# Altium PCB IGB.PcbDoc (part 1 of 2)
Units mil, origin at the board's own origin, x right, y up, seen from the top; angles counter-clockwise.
Board outline 7000 x 12000 mil, 4 copper layers (Top Layer, GND, PWR, Bottom Layer), stack 55.52 mil thick; 229 components, 204 nets, 726 pads, 127 vias.
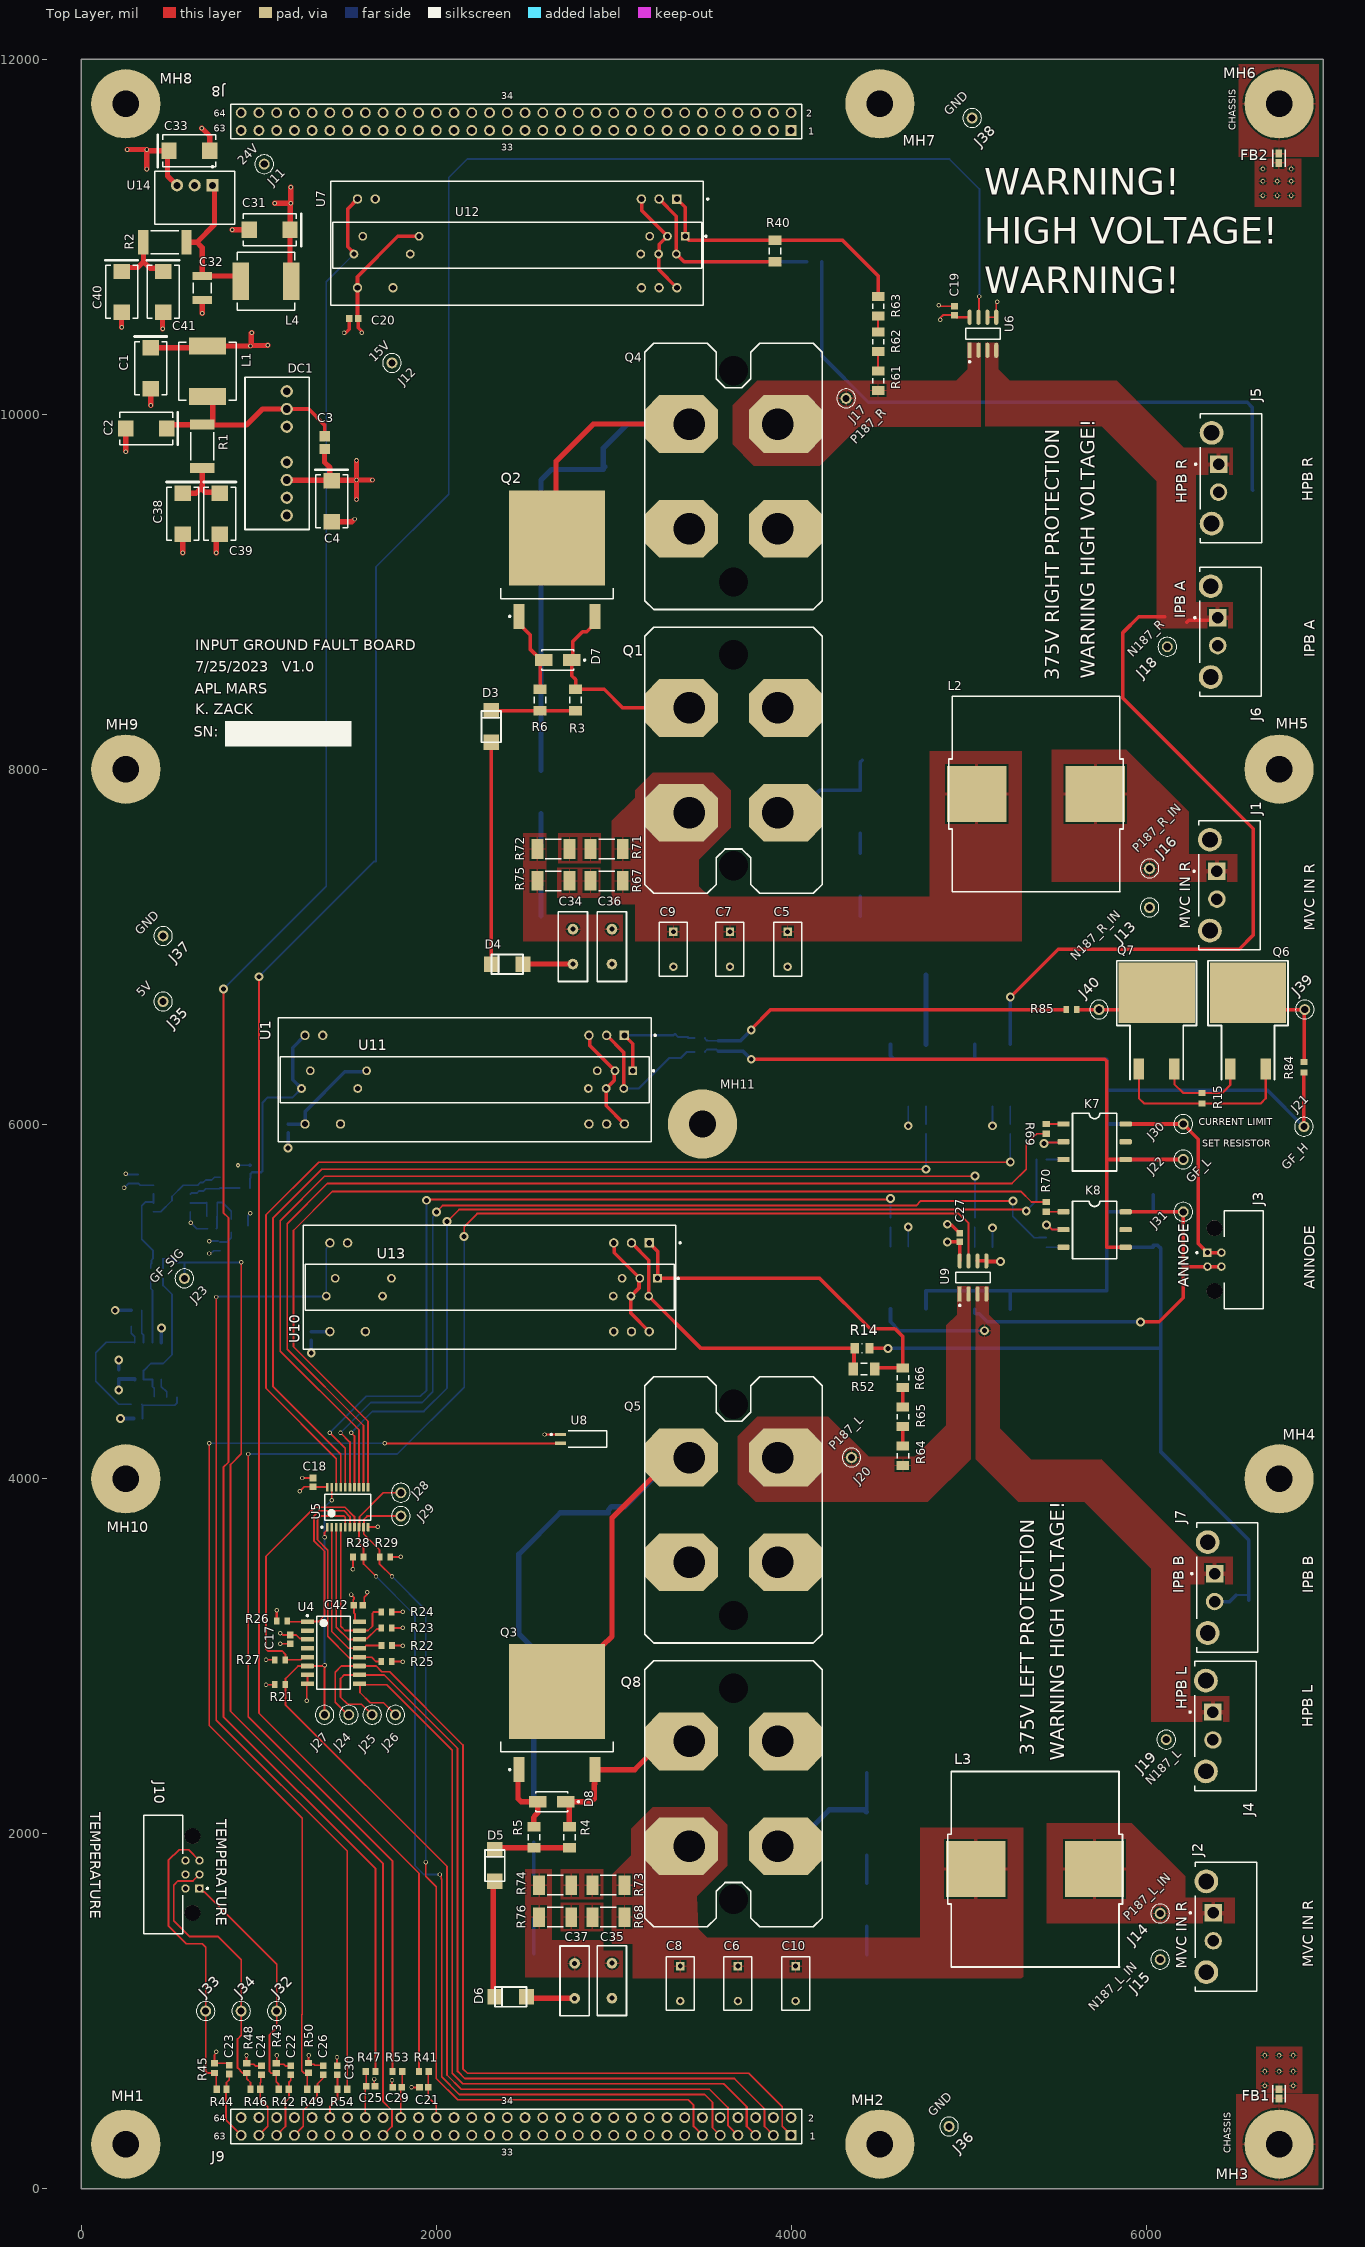
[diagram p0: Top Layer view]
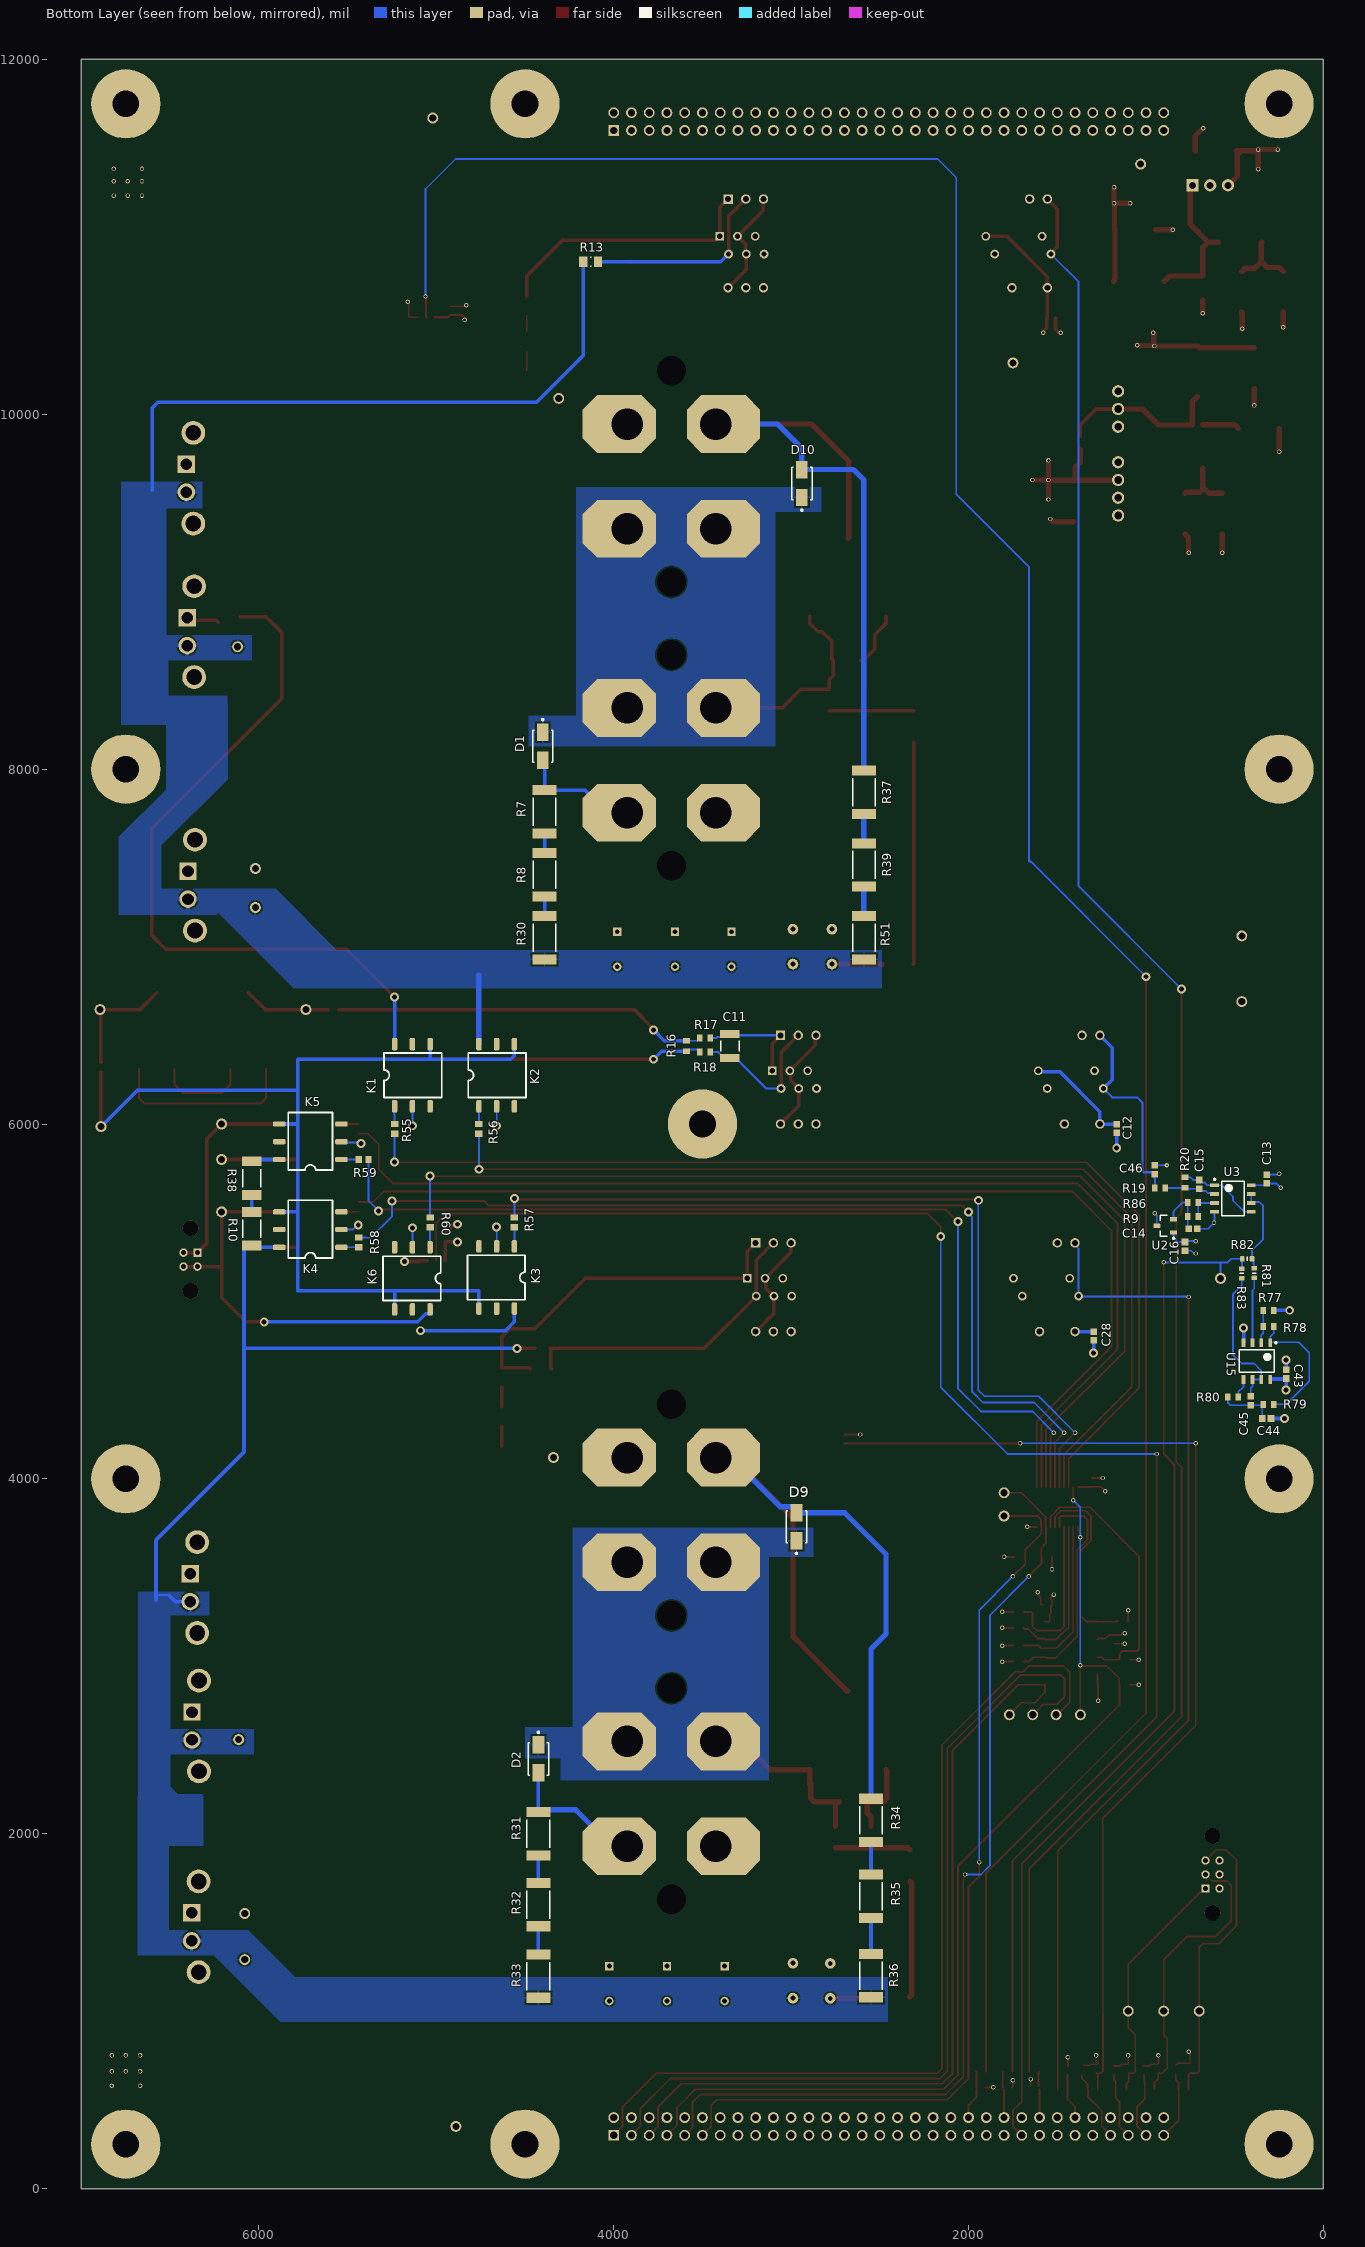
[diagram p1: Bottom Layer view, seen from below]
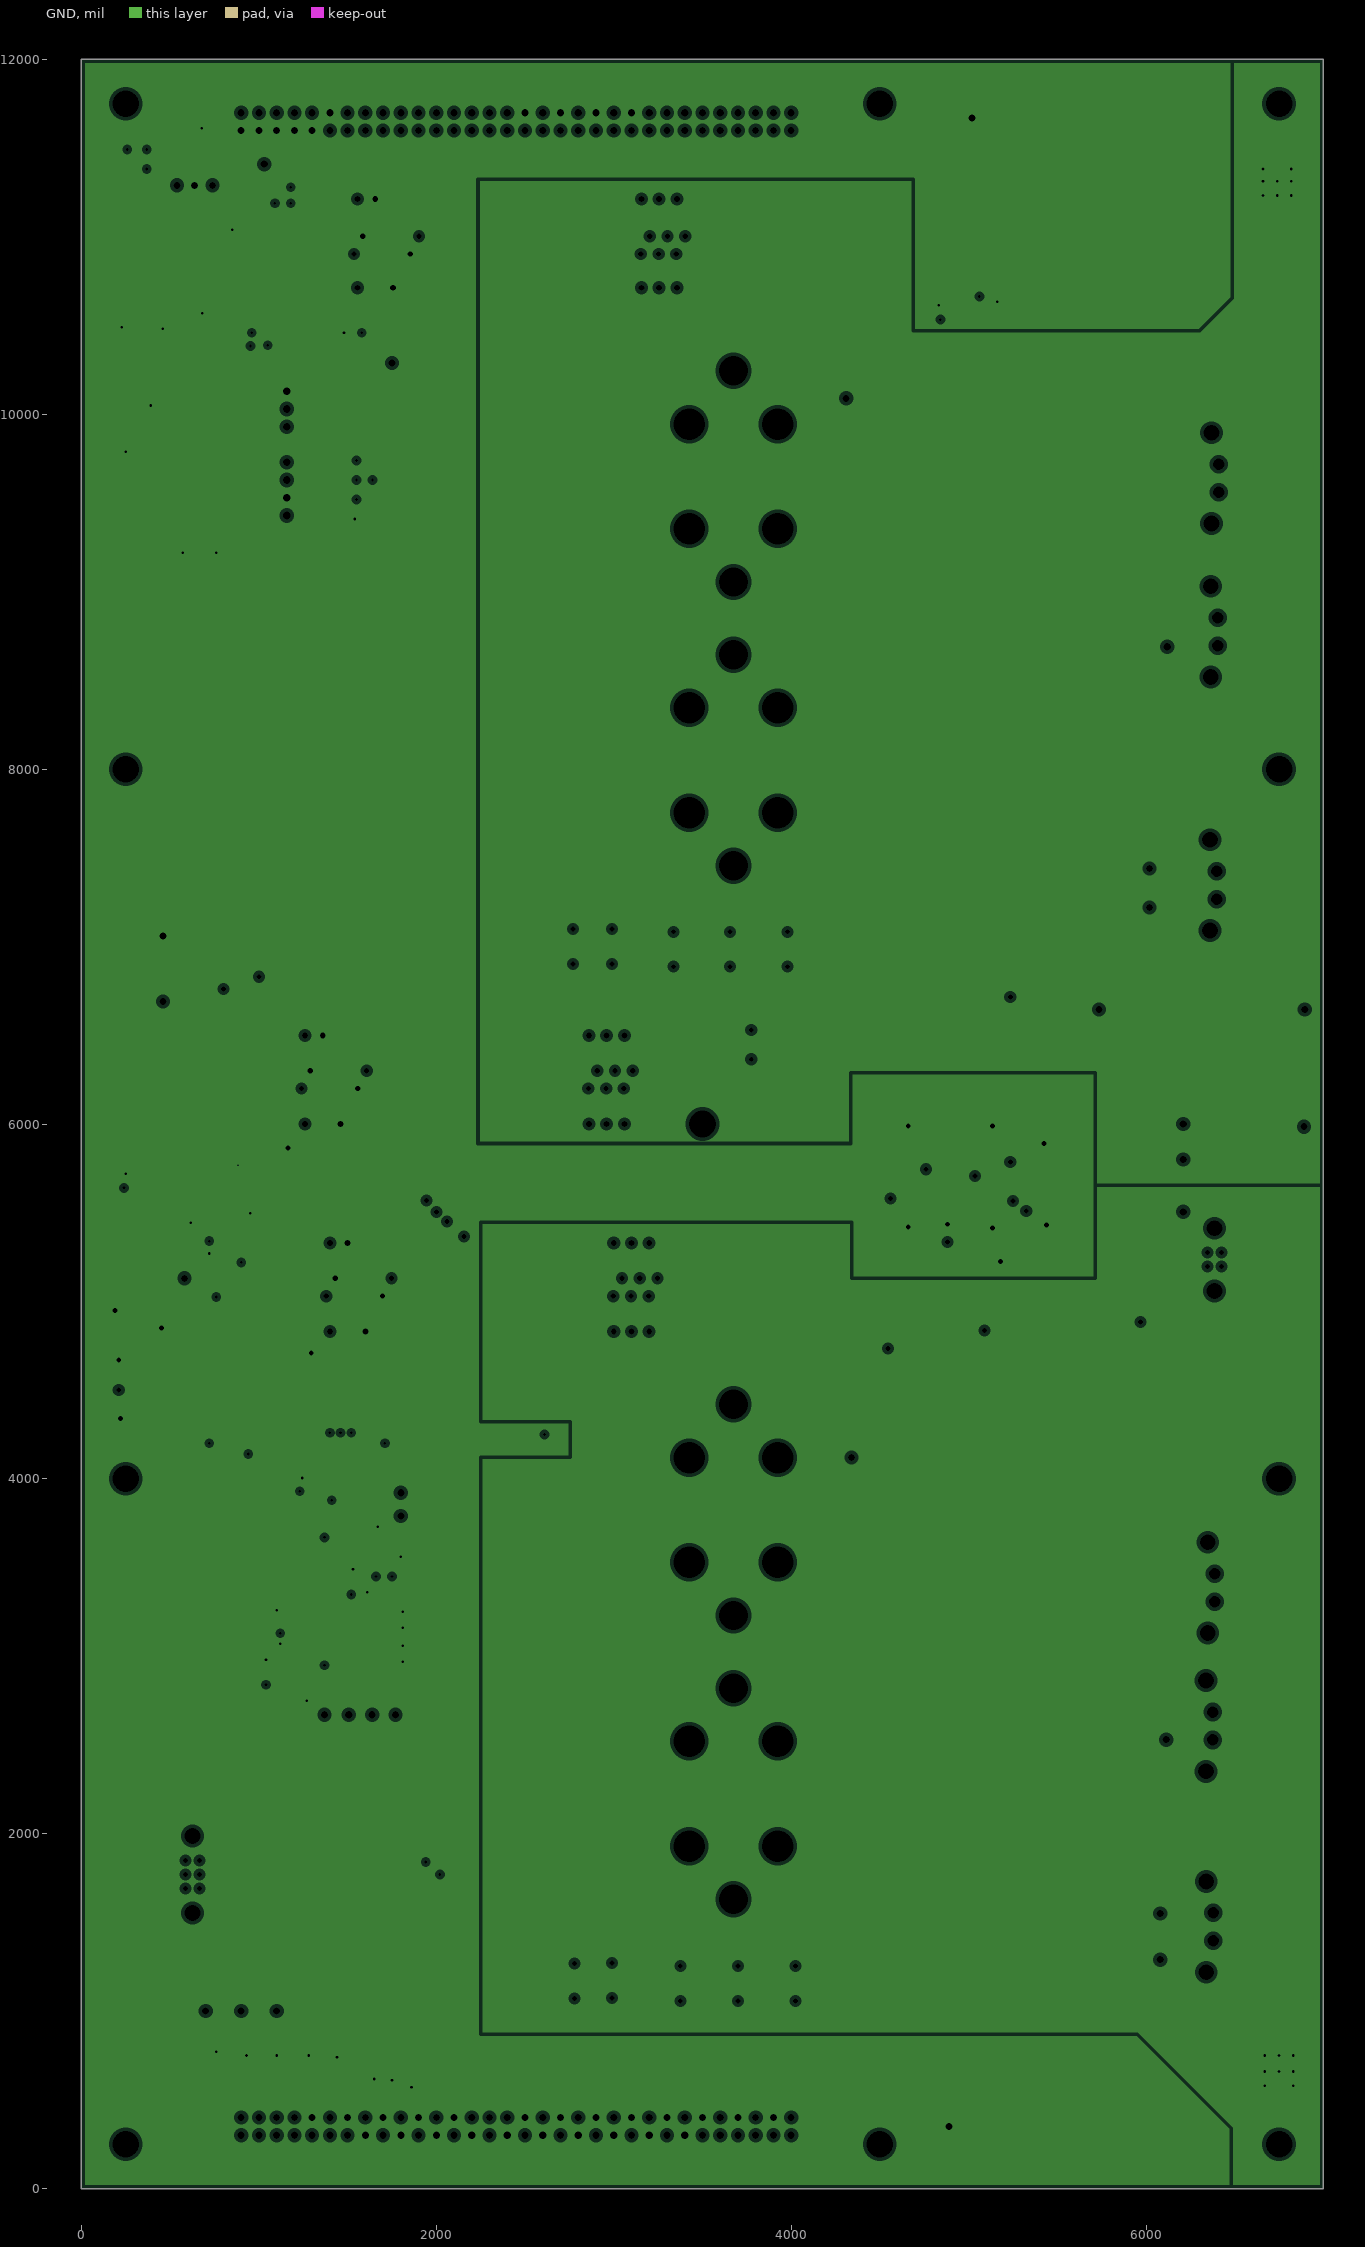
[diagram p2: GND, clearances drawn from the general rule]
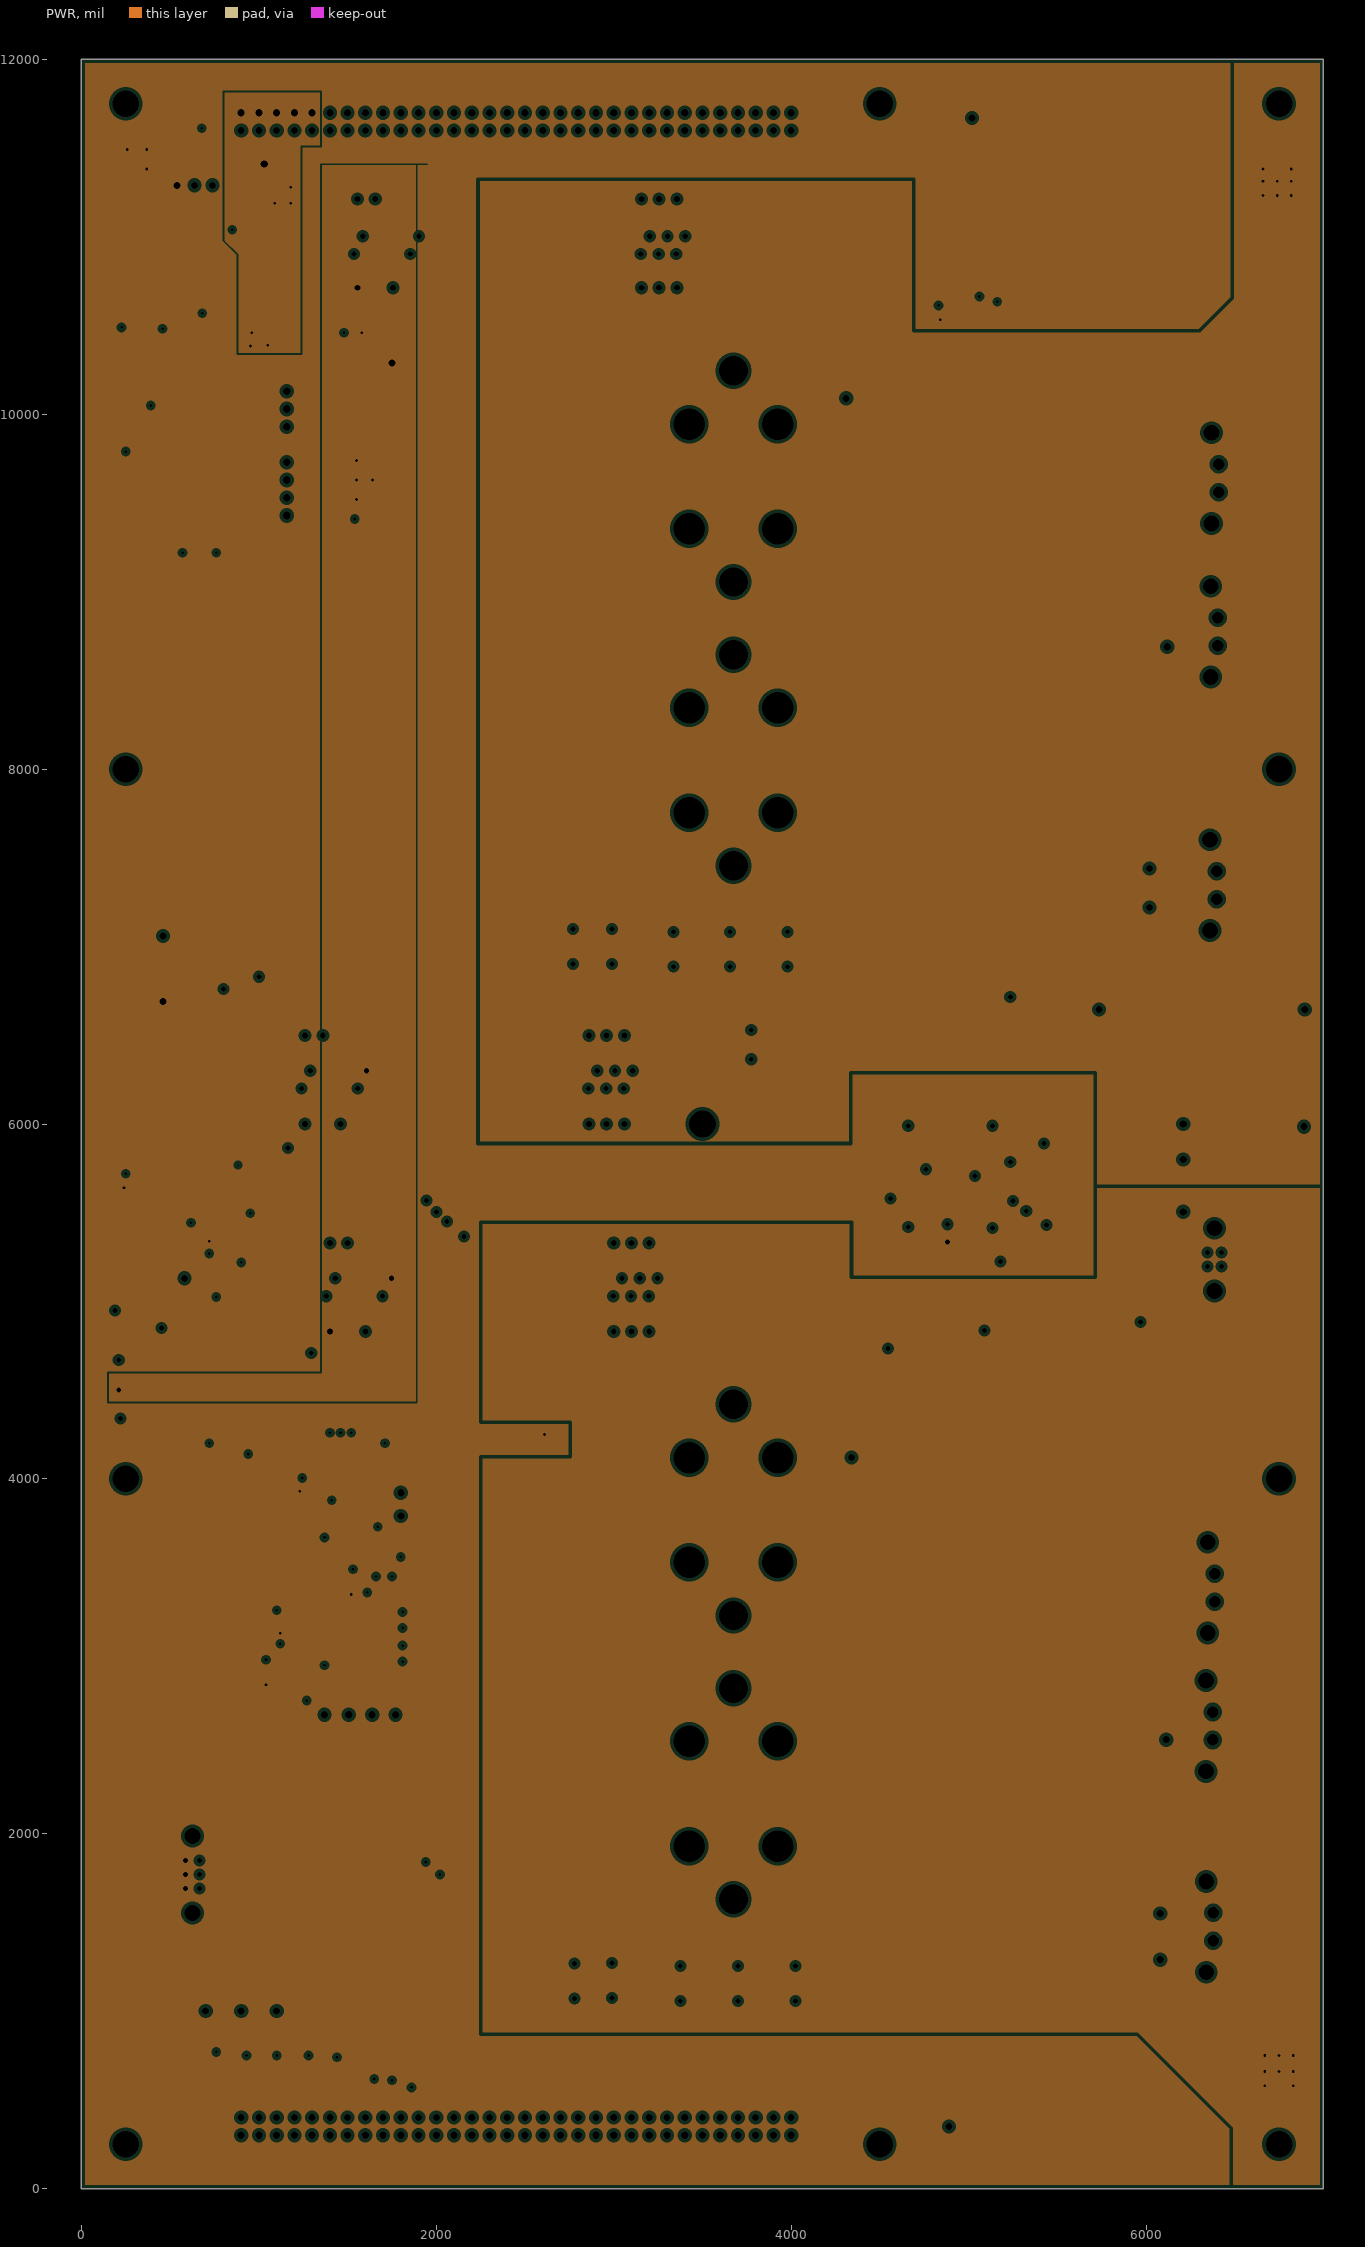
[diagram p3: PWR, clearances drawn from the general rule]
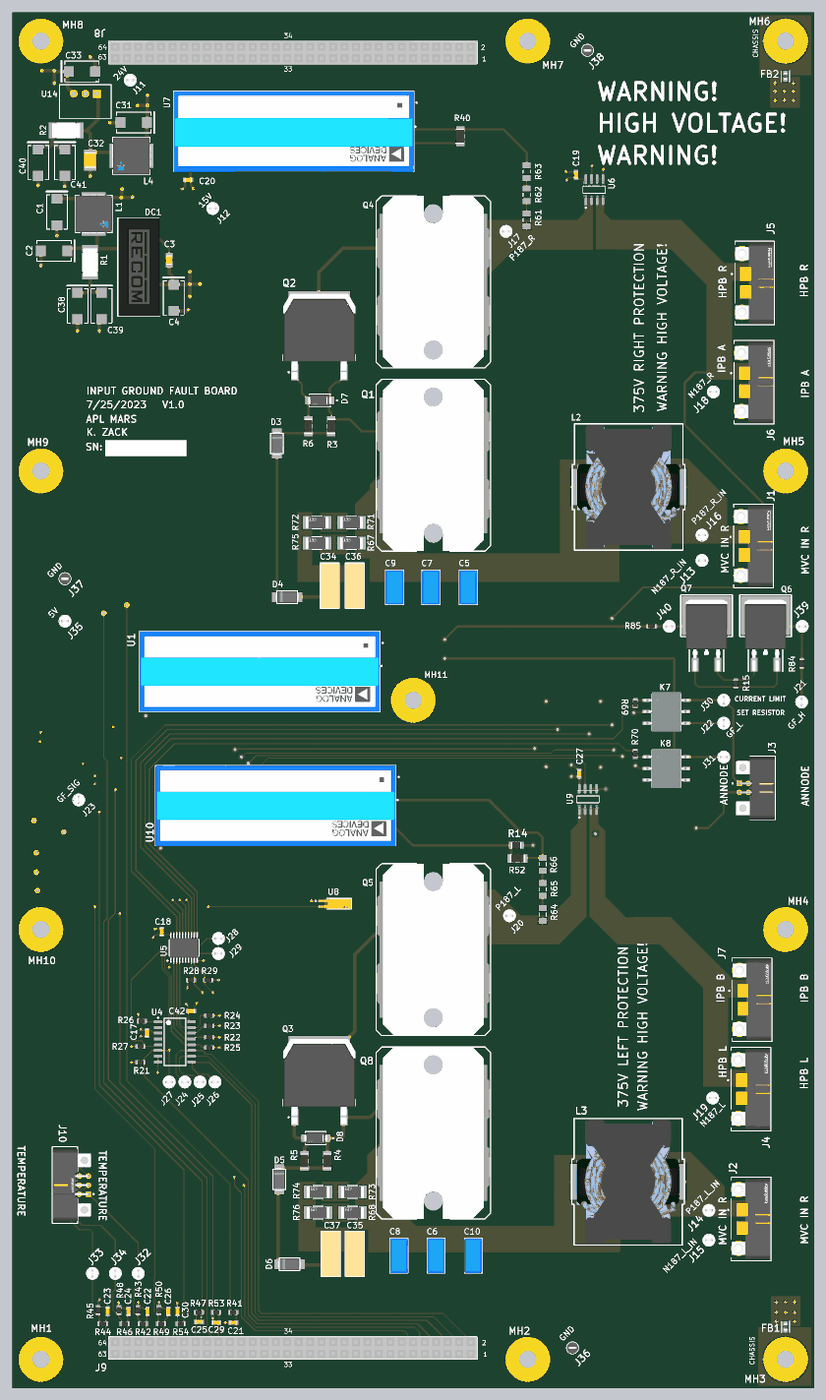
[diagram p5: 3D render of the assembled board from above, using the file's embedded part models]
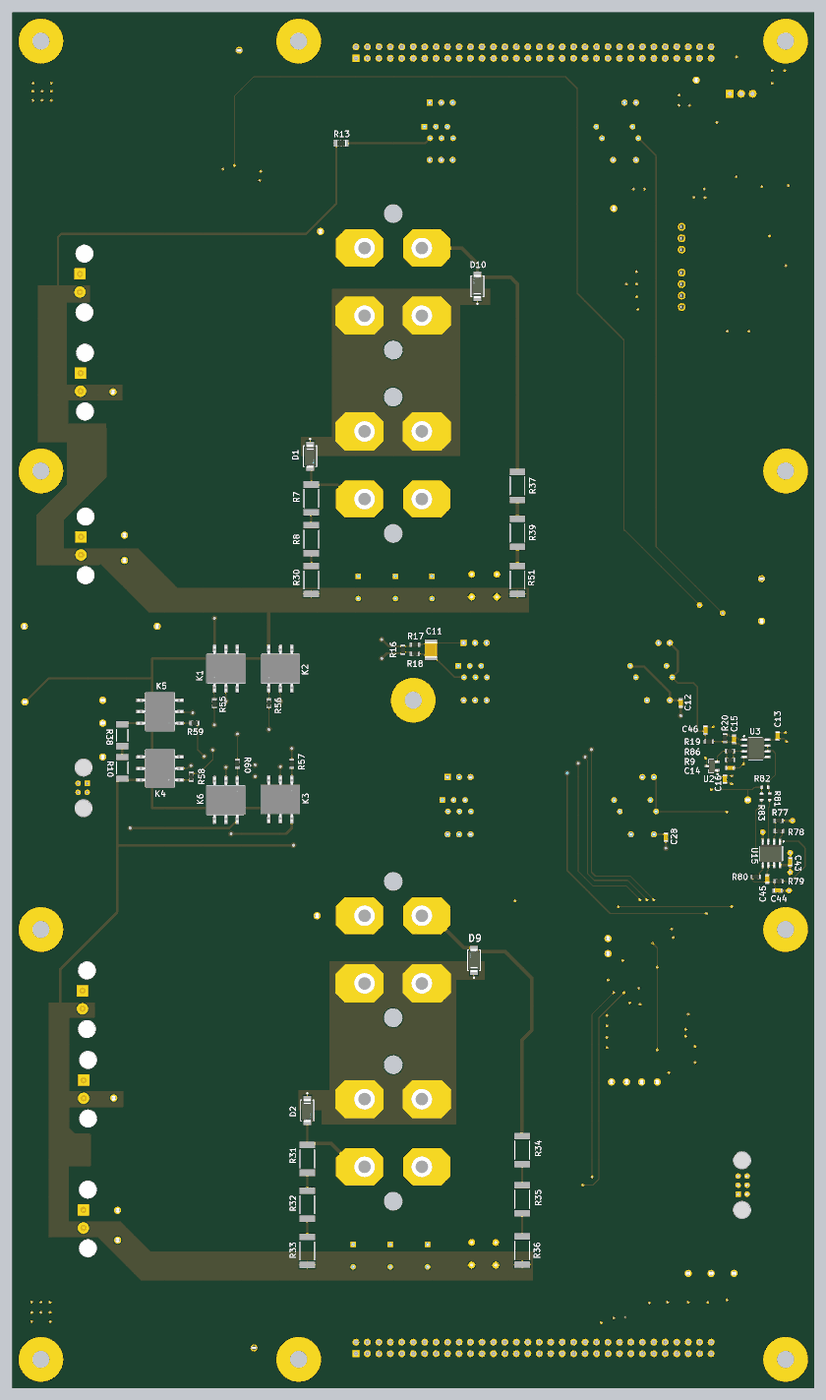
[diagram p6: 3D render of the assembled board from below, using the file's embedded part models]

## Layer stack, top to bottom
Top Solder: solder mask 0.4, Solder Resist, Dk 3.5
Top Layer: signal copper 1.7
Dielectric 1: prepreg 7.96, PP-013, Dk 4.3
GND: plane copper 0.68, net (Multiple Nets)
Core 1: core 39, FR-4, Dk 4.8
PWR: plane copper 0.68, net (Multiple Nets)
Dielectric 2: prepreg 3.8, PP-013, Dk 4.3
Bottom Layer: signal copper 1.7
Bottom Solder: solder mask 0.4, Solder Resist, Dk 3.5

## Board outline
0,0 0,12000 7000,12000 7000,0

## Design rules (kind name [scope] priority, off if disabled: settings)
Clearance [All] p1: gap=8 ignorepadtopadclearanceinfootprint=FALSE except(0: Arc-Hole Track-Hole SMDPad-Hole THPad-Hole Via-Hole Fill-Hole Poly-Hole Region-Hole Text-Hole; 10: SMDPad-THPad SMDPad-Via SMDPad-Text THPad-THPad THPad-Via THPad-Text Via-Via Via-Text Fill-Text Poly-Text Region-Text Text-Text)
ComponentClearance "Amplifier Exception Voltage R" [InComponent('U7') vs InComponent('U12')] p1: gap=0 collisioncheckmode=3 verticalgap=0 showdistances=FALSE checkcomponentboundary=TRUE
ComponentClearance "Amplifier Exception Voltage L" [InComponent('U10') vs InComponent('U13')] p2: gap=0 collisioncheckmode=3 verticalgap=0 showdistances=FALSE checkcomponentboundary=TRUE
ComponentClearance "Amplifier Exception GF" [InComponent('U11') vs InComponent('U1')] p3: gap=0 collisioncheckmode=3 verticalgap=0 showdistances=FALSE donotcheckwithout3dbody=TRUE // U1 Clearance
ComponentClearance [All] p4: gap=10 collisioncheckmode=3 verticalgap=10 showdistances=FALSE
HoleSize [All] p1: absolutevalues=TRUE maxlimit=250 minlimit=1 maxpercent=80.000 minpercent=20.000
MinimumSolderMaskSliver [All] p1: minsoldermaskwidth=3.8
PlaneClearance [All] p1: clearance=20
PlaneConnect [All] p1: planeconnectstyle=Relief reliefexpansion=20 reliefentries=4 reliefconductorwidth=10 reliefairgap=10
PolygonConnect [All] p1: connectstyle=Relief reliefconductorwidth=10 reliefentries=4 polygonreliefangle="90 Angle" airgapwidth=10
RoutingVias [All] p1: holewidth=28 width=50 viastyle="Through Hole" minholewidth=28 minwidth=50 maxholewidth=28 maxwidth=50
SolderMaskExpansion [All] p1: expansion=4 istentingtop=FALSE
Width [All] p1: maxlimit=100 minlimit=6 preferedwidth=20 minimp=50.000000 maximp=50.000000 favimp=50.000000
25 further rules are at their usual default settings.

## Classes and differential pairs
component class Sensors: C19 C20 C21 C22 C23 C24 C25 C26 C27 C28 C29 C30 J32 J33 J34 R40 R41 R42 R43 R44 R45 R46 R47 R48 R49 R50 R52 R53 R54 R61 R62 R63 R64 R65 R66 U6 U7 U8 U9 U10 U12 U13
component class "Power Suppies": C1 C2 C3 C4 C31 C32 C33 C38 C39 C40 C41 DC1 J11 J12 J35 J36 J37 J38 L1 L4 R1 R2 U14
component class "GF Switch": C17 C18 C42 J24 J25 J26 J27 J28 J29 J30 J31 K1 K2 K3 K4 K5 K6 K7 K8 R10 R21 R22 R23 R24 R25 R26 R27 R28 R29 R38 R55 R56 R57 R58 R59 R60 R69 R70 U4 U5
component class "GF Detect": C11 C12 C13 C14 C15 C16 C43 C44 C45 C46 J21 J22 J23 J39 J40 Q6 Q7 R9 R15 R16 R17 R18 R19 R20 R77 R78 R79 R80 R81 R82 R83 R84 R85 R86 U1 U2 U3 U11 U15
component class U_Connectors: J1 J2 J3 J4 J5 J6 J7 J8 J9 J10
component class Input: C5 C6 C7 C8 C9 C10 C34 C35 C36 C37 D1 D2 D3 D4 D5 D6 D7 D8 D9 D10 J13 J14 J15 J16 J17 J18 J19 J20 L2 L3 Q1 Q2 Q3 Q4 Q5 Q8 R3 R4 R5 R6 R7 R8 R13 R14 R30 R31 R32 R33 R34 R35 R36 R37 R39 R51 R67 R68 R71 R72 R73 R74 R75 R76
component class Coversheet: FB1 FB2 MH1 MH2 MH3 MH4 MH5 MH6 MH7 MH8 MH9 MH10 MH11

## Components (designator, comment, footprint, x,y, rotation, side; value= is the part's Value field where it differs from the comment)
C1 "T491D106K050AT" KEMT-D-7343-31-2_L 390,10260 r270 top value=10uF
C2 "T491D106K050AT" KEMT-D-7343-31-2_L 364.84,9920 r180 top value=10uF
C3 "Capacitor 330pF 10%, 50V, X7R, 0805" CAPC2013X95X50ML10T25 1370,9840 r270 top value=330pF
C4 "T491D106K050AT" KEMT-D-7343-31-2_L 1410,9510 r270 top value=10uF
C5 "Capacitor 0.22uF, 20%, 1kV,X7R,Radial" FP-RDEUE1+0_5-MFG 3980,6985 r270 top value=220nF
C6 "Capacitor 0.22uF, 20%, 1kV,X7R,Radial" FP-RDEUE1+0_5-MFG 3700,1155 r270 top value=220nF
C7 "Capacitor 0.22uF, 20%, 1kV,X7R,Radial" FP-RDEUE1+0_5-MFG 3655,6985 r270 top value=220nF
C8 "Capacitor 0.22uF, 20%, 1kV,X7R,Radial" FP-RDEUE1+0_5-MFG 3375,1155 r270 top value=220nF
C9 "Capacitor 0.22uF, 20%, 1kV,X7R,Radial" FP-RDEUE1+0_5-MFG 3336.26,6985 r270 top value=220nF
C10 "Capacitor 0.22uF, 20%, 1kV,X7R,Radial" FP-RDEUE1+0_5-MFG 4025,1155 r270 top value=220nF
C11 "Capacitor 2.2uF 10%, 50V, X7R, 1210" CAPC3225X270X30ML30 3345,6440 r90 bottom value=2.2uF
C12 "Capacitor 100 nF +/-10% 50 V 0603" CAPC1608X90X40NL10T20 1165,5975 r90 bottom value=100nF
C13 "Capacitor 100 nF +/-10% 50 V 0603" CAPC1608X90X40NL10T20 320,5690 r270 bottom value=100nF
C14 "Capacitor 100 nF +/-10% 50 V 0603" CAPC1608X90X40NL10T20 735,5410 r0 bottom value=100nF
C15 "Capacitor 100 nF +/-10% 50 V 0603" CAPC1608X90X40NL10T20 700,5660 r90 bottom value=100nF
C16 "Capacitor 100 nF +/-10% 50 V 0603" CAPC1608X90X40NL10T20 780,5310 r90 bottom value=100nF
C17 "Capacitor 100 nF +/-10% 50 V 0603" CAPC1608X90X40NL10T20 1175.74,3095.5 r90 top value=100nF
C18 "Capacitor 100 nF +/-10% 50 V 0603" CAPC1608X90X40NL10T20 1304.95,3980 r270 top value=100nF
C19 "Capacitor 100 nF +/-10% 50 V 0603" CAPC1608X90X40NL10T20 4921,10584 r270 top value=100nF
C20 "Capacitor 100 nF +/-10% 50 V 0603" CAPC1608X90X40NL10T20 1534.61,10540 r0 top value=100nF
C21 "Capacitor 100 nF +/-10% 50 V 0603" CAPC1608X90X40NL10T20 1930,570 r0 top value=100nF
C22 "Capacitor 100 nF +/-10% 50 V 0603" CAPC1608X90X40NL10T20 1180,666.47 r270 top value=100nF
C23 "Capacitor 100 nF +/-10% 50 V 0603" CAPC1608X90X40NL10T20 832.84,670 r270 top value=100nF
C24 "Capacitor 100 nF +/-10% 50 V 0603" CAPC1608X90X40NL10T20 1014.31,666.47 r270 top value=100nF
C25 "Capacitor 100 nF +/-10% 50 V 0603" CAPC1608X90X40NL10T20 1630,577.16 r180 top value=100nF
C26 "Capacitor 100 nF +/-10% 50 V 0603" CAPC1608X90X40NL10T20 1362.84,666.47 r270 top value=100nF
C27 "Capacitor 100 nF +/-10% 50 V 0603" CAPC1608X90X40NL10T20 4950,5360 r270 top value=100nF
C28 "Capacitor 100 nF +/-10% 50 V 0603" CAPC1608X90X40NL10T20 1295,4805.39 r90 bottom value=100nF
C29 "Capacitor 100 nF +/-10% 50 V 0603" CAPC1608X90X40NL10T20 1780,570 r0 top value=100nF
C30 "Capacitor 100 nF +/-10% 50 V 0603" CAPC1608X90X40NL10T20 1442.44,666.47 r270 top value=100nF
C31 "T491D106K050AT" KEMT-D-7343-31-2_L 1060,11040 r180 top value=10uF
C32 "Capacitor 4.7uF 10%, 50V, X7R, 1210" CAPC3225X270X30ML30 680,10712.09 r90 top value=4.7uF
C33 "T491D106K050AT" KEMT-D-7343-31-2_L 608.16,11485 r0 top value=10uF
C34 "Capacitor 1.2uF 20% 500V X7R" "Capacitor 1.2uF 20% 500V X7R-Footprint-1" 2770,7000 r90 top value=1.2uF
C35 "Capacitor 1.2uF 20% 500V X7R" "Capacitor 1.2uF 20% 500V X7R-Footprint-1" 2990,1171.57 r90 top value=1.2uF
C36 "Capacitor 1.2uF 20% 500V X7R" "Capacitor 1.2uF 20% 500V X7R-Footprint-1" 2990,7000 r90 top value=1.2uF
C37 "Capacitor 1.2uF 20% 500V X7R" "Capacitor 1.2uF 20% 500V X7R-Footprint-1" 2779.61,1170.39 r90 top value=1.2uF
C38 "T491D106K050AT" KEMT-D-7343-31-2_L 570,9440 r270 top value=10uF
C39 "T491D106K050AT" KEMT-D-7343-31-2_L 780,9440 r270 top value=10uF
C40 "T491D106K050AT" KEMT-D-7343-31-2_L 226.02,10690 r270 top value=10uF
C41 "T491D106K050AT" KEMT-D-7343-31-2_L 460,10690 r270 top value=10uF
C42 "Capacitor 100 nF +/-10% 50 V 0603" CAPC1608X90X40NL10T20 1560,3287.88 r180 top value=100nF
C43 "Capacitor 100 nF +/-10% 50 V 0603" CAPC1608X90X40NL10T20 210,4590 r270 bottom value=100nF
C44 "Capacitor 100 nF +/-10% 50 V 0603" CAPC1608X90X40NL10T20 320,4340 r0 bottom value=100nF
C45 "Capacitor 100 nF +/-10% 50 V 0603" CAPC1608X90X40NL10T20 410,4440 r90 bottom value=100nF
C46 "Capacitor 100 nF +/-10% 50 V 0603" CAPC1608X90X40NL10T20 950,5742 r270 bottom value=100nF
D1 "SMAZ15-13-F" FP-SMA-MFG 4400,8128.74 r270 bottom
D2 "SMAZ15-13-F" FP-SMA-MFG 4425,2421.26 r270 bottom
D3 "BZG03C200-M3-08" BZG03C200-M3-08-Footprint-1 2310,8240 r90 top
D4 "BZG03C200-M3-08" BZG03C200-M3-08-Footprint-1 2400,6900 r180 top
D5 "BZG03C200-M3-08" BZG03C200-M3-08-Footprint-1 2330,1820 r90 top
D6 "BZG03C200-M3-08" BZG03C200-M3-08-Footprint-1 2420,1080 r180 top
D7 "SMAZ15-13-F" FP-SMA-MFG 2685,8615 r180 top
D8 "SMAZ15-13-F" FP-SMA-MFG 2650,2180 r180 top
D9 "SMAZ15-13-F" FP-SMA-MFG 2970,3730 r90 bottom
D10 "SMAZ15-13-F" FP-SMA-MFG 2940,9610 r90 bottom
DC1 "RS3-2415S/H3" RS3-2415S_H3-Footprint-1 1057.18,9780 r270 top
FB1 "BLM18SG121TN1D" FP-BLM18-0_15-t0_5-d1_2-IPC_B 6750,533.38 r270 top
FB2 "BLM18SG121TN1D" FP-BLM18-0_15-t0_5-d1_2-IPC_B 6749,11443 r90 top
J1 "M80-5000000M5-02-333-00-000" FP-M80-5000000M5-02-333-0-MFG 6470.48,7346.26 r90 top
J2 "M80-5000000M5-02-333-00-000" FP-M80-5000000M5-02-333-0-MFG 6450,1475 r90 top
J3 "M80-5400442" M80-5400442-Footprint-1 6385.63,5235.63 r90 top
J4 "M80-5000000M5-02-333-00-000" FP-M80-5000000M5-02-333-0-MFG 6448,2607 r90 top
J5 "M80-5000000M5-02-333-00-000" FP-M80-5000000M5-02-333-0-MFG 6480,9640 r90 top
J6 "M80-5000000M5-02-333-00-000" FP-M80-5000000M5-02-333-0-MFG 6475,8775 r90 top
J7 "M80-5000000M5-02-333-00-000" FP-M80-5000000M5-02-333-0-MFG 6458,3387 r90 top
J8 "ESQ-132-14-G-D" SMTC-ESQ-132-14-X-D 4000,11600 r180 top
J9 "ESQ-132-14-G-D" SMTC-ESQ-132-14-X-D 4000,300 r180 top
J10 "M80-5400642" FP-M80-5400642-MFG 460,1770 r270 top
J11 "5002" FP-5002-MFG 1030,11410 r180 top
J12 "5002" FP-5002-MFG 1750,10290 r180 top
J13 "5002" FP-5002-MFG 6020,7220 r180 top
J14 "5002" FP-5002-MFG 6080,1550 r180 top
J15 "5002" FP-5002-MFG 6080,1290 r180 top
J16 "5002" FP-5002-MFG 6020,7440 r180 top
J17 "5002" FP-5002-MFG 4310,10090 r180 top
J18 "5002" FP-5002-MFG 6120,8690 r180 top
J19 "5002" FP-5002-MFG 6114,2530 r180 top
J20 "5002" FP-5002-MFG 4340,4120 r180 top
J21 "5002" FP-5002-MFG 6890,5985 r270 top
J22 "5002" FP-5002-MFG 6210,5800 r90 top
J23 "5002" FP-5002-MFG 580,5130 r270 top
J24 "5002" FP-5002-MFG 1506.67,2670 r0 top
J25 "5002" FP-5002-MFG 1638.34,2670 r0 top
J26 "5002" FP-5002-MFG 1770,2670 r0 top
J27 "5002" FP-5002-MFG 1370,2670 r0 top
J28 "5002" FP-5002-MFG 1800,3921.66 r0 top
J29 "5002" FP-5002-MFG 1800,3790 r0 top
J30 "5002" FP-5002-MFG 6210,6000 r90 top
J31 "5002" FP-5002-MFG 6210,5505 r180 top
J32 "5002" FP-5002-MFG 1100,1000 r90 top
J33 "5002" FP-5002-MFG 700,1000 r90 top
J34 "5002" FP-5002-MFG 900,1000 r90 top
J35 "5002" FP-5002-MFG 460,6690 r180 top
J36 "5001" FP-5001-MFG 4890,350 r180 top
J37 "5001" FP-5001-MFG 460,7060 r0 top
J38 "5001" FP-5001-MFG 5020,11670 r0 top
J39 "5002" FP-5002-MFG 6895,6645 r0 top
J40 "5002" FP-5002-MFG 5735,6645 r0 top
K1 "PLA143S" PLA143S-Footprint-1 5135,6275 r180 bottom
K2 "PLA143S" PLA143S-Footprint-1 4660,6275 r180 bottom
K3 "PLA143S" PLA143S-Footprint-1 4660,5135 r0 bottom
K4 "PLA143S" PLA143S-Footprint-1 5710,5405 r90 bottom
K5 "PLA143S" PLA143S-Footprint-1 5710,5900 r90 bottom
K6 "PLA143S" PLA143S-Footprint-1 5135,5130 r0 bottom
K7 "PLA143S" PLA143S-Footprint-1 5710,5900 r270 top
K8 "PLA143S" PLA143S-Footprint-1 5710,5405 r270 top
L1 "IHLP3232DZER5R6M01" FP-IHLP-3232DZ-FP_2_413x5-MFG 710,10242.5 r270 top value=5.6uH
L2 "74437529203221" 74437529203221-Footprint-1 5380,7860 r90 top value=220uH
L3 "74437529203221" 74437529203221-Footprint-1 5375,1800 r90 top value=220uH
L4 "IHLP3232DZER5R6M01" FP-IHLP-3232DZ-FP_2_413x5-MFG 1040,10749.73 r180 top value=5.6uH
MH1 "MH-MARS2-6-32" "MH-M3-Footprint-1 - Oversized MARS2" 250,250 r0 top
MH2 "MH-MARS2-6-32" "MH-M3-Footprint-1 - Oversized MARS2" 4500,250 r180 top locked
MH3 "MH-MARS2-6-32" "MH-M3-Footprint-1 - Oversized MARS2" 6750,250 r180 top locked
MH4 "MH-MARS2-6-32" "MH-M3-Footprint-1 - Oversized MARS2" 6750,4000 r180 top locked
MH5 "MH-MARS2-6-32" "MH-M3-Footprint-1 - Oversized MARS2" 6750,8000 r180 top locked
MH6 "MH-MARS2-6-32" "MH-M3-Footprint-1 - Oversized MARS2" 6750,11750 r0 top
MH7 "MH-MARS2-6-32" "MH-M3-Footprint-1 - Oversized MARS2" 4500,11750 r0 top
MH8 "MH-MARS2-6-32" "MH-M3-Footprint-1 - Oversized MARS2" 250,11750 r180 top locked
MH9 "MH-MARS2-6-32" "MH-M3-Footprint-1 - Oversized MARS2" 250,8000 r180 top
MH10 "MH-MARS2-6-32" "MH-M3-Footprint-1 - Oversized MARS2" 250,4000 r180 top locked
MH11 "MH-MARS2-6-32" "MH-M3-Footprint-1 - Oversized MARS2" 3500,6000 r180 top
Q1 "IXTN32P60P" IXTN32P60P-Footprint-1 3675,8050 r90 top
Q2 "IXTT16P60P" DPAK545P1890X510-3N 2680,9180 r90 top
Q3 "IXTT16P60P" DPAK545P1890X510-3N 2680,2680 r90 top
Q4 "IXTN32P60P" IXTN32P60P-Footprint-1 3675,9650 r270 top
Q5 "IXTN32P60P" IXTN32P60P-Footprint-1 3675,3825 r270 top
Q6 "IXTA1R6N100D2HV" IXTA1R6N100D2HV-Footprint-1 6575,6580 r0 top
Q7 "IXTA1R6N100D2HV" IXTA1R6N100D2HV-Footprint-1 6060,6580 r0 top
Q8 "IXTN32P60P" IXTN32P60P-Footprint-1 3675,2225 r90 top
R1 "Resistor 1R0 1% 2512 1W" FP-CRCW2512-e3-MFG 680,9820 r90 top
R2 "Resistor 1R0 1% 2512 1W" FP-CRCW2512-e3-MFG 470,10970 r0 top
R3 "Resistor 100k +/-1% 1206 250 mW" RESC3216X60X45ML15T20 2785,8390 r90 top value=100k
R4 "Resistor 100k +/-1% 1206 250 mW" RESC3216X60X45ML15T20 2750,1980.04 r90 top value=100k
R5 "Resistor 100k +/-1% 1206 250 mW" RESC3216X60X45ML15T20 2550,1980.04 r90 top value=100k
R6 "Resistor 100k +/-1% 1206 250 mW" RESC3216X60X45ML15T20 2585,8390 r90 top value=100k
R7 "Resistor 33K 5% 2512 1W" RESC2512(6432)_M 4390,7760 r90 bottom
R8 "Resistor 33K 5% 2512 1W" RESC2512(6432)_M 4390,7404.5 r90 bottom
R9 "Resistor 47K5 +/-1% 0603 100 mW" RESC1608X55X25ML10T15 735,5480 r180 bottom value=47.5k
R10 "RC2010FK-071ML" RESC5025X06M 6040,5410 r270 bottom value=1MR
R13 "Resistor 0R +/- 1% 0805 125 mW" RESC2013X50X35ML15T15 4130,10860 r180 bottom value=0
R14 "Resistor 0R +/- 1% 0805 125 mW" RESC2013X50X35ML15T15 4400,4735 r180 top value=0
R15 "Resistor 2K43+/-1% 0603 100 mW" RESC1608X55X25ML10T15 6315,6145 r90 top value=2.43k
R16 "Resistor 2K43+/-1% 0603 100 mW" RESC1608X55X25ML10T15 3590,6440 r90 bottom value=2.43k
R17 "Resistor 47K5 +/-1% 0603 100 mW" RESC1608X55X25ML10T15 3485,6485 r180 bottom value=47.5k
R18 "Resistor 47K5 +/-1% 0603 100 mW" RESC1608X55X25ML10T15 3485.47,6405 r180 bottom value=47.5k
R19 "Resistor 47K5 +/-1% 0603 100 mW" RESC1608X55X25ML10T15 920,5640 r180 bottom value=47.5k
R20 "Resistor 47K5 +/-1% 0603 100 mW" RESC1608X55X25ML10T15 780.88,5670 r90 bottom value=47.5k
R21 "Resistor 100k +/-1% 0603 100 mW" RESC1608X55X25ML10T15 1120,2840 r0 top value=100k
R22 "Resistor 100k +/-1% 0603 100 mW" RESC1608X55X25ML10T15 1720.47,3060 r180 top value=100k
R23 "Resistor 100k +/-1% 0603 100 mW" RESC1608X55X25ML10T15 1720,3159.28 r180 top value=100k
R24 "Resistor 100k +/-1% 0603 100 mW" RESC1608X55X25ML10T15 1720,3250 r180 top value=100k
R25 "Resistor 100k +/-1% 0603 100 mW" RESC1608X55X25ML10T15 1719.53,2969.28 r180 top value=100k
R26 "Resistor 100k +/-1% 0603 100 mW" RESC1608X55X25ML10T15 1130,3200 r0 top value=100k
R27 "Resistor 100k +/-1% 0603 100 mW" RESC1608X55X25ML10T15 1120,2980 r0 top value=100k
R28 "Resistor 100k +/-1% 0603 100 mW" RESC1608X55X25ML10T15 1560,3560 r0 top value=100k
R29 "Resistor 100k +/-1% 0603 100 mW" RESC1608X55X25ML10T15 1710,3560 r180 top value=100k
R30 "Resistor 33K 5% 2512 1W" RESC2512(6432)_M 4390,7050 r90 bottom
R31 "Resistor 33K 5% 2512 1W" RESC2512(6432)_M 4425,2000 r90 bottom
R32 "Resistor 33K 5% 2512 1W" RESC2512(6432)_M 4425,1600 r90 bottom
R33 "Resistor 33K 5% 2512 1W" RESC2512(6432)_M 4425,1197.05 r90 bottom
R34 "Resistor 33K 5% 2512 1W" RESC2512(6432)_M 2550,2075 r90 bottom
R35 "Resistor 33K 5% 2512 1W" RESC2512(6432)_M 2550,1647.05 r90 bottom
R36 "Resistor 33K 5% 2512 1W" RESC2512(6432)_M 2550,1200 r90 bottom
R37 "Resistor 33K 5% 2512 1W" RESC2512(6432)_M 2590,7870 r90 bottom
R38 "RC2010FK-071ML" RESC5025X06M 6040,5695 r270 bottom value=1MR
R39 "Resistor 33K 5% 2512 1W" RESC2512(6432)_M 2590,7460 r90 bottom
R40 "Resistor 10k +/-1% 1206 250 mW" RESC3216X60X45ML15T20 3910,10920 r90 top value=10k
R41 "Resistor 51R1 +/-1% 0603 100 mW" RESC1609X50X30ML08T20 1930,660 r0 top value=51.1
R42 "Resistor 51R1 +/-1% 0603 100 mW" RESC1609X50X30ML08T20 1140,560 r180 top value=51.1
R43 "Resistor 7K15 +/-1% 0603 100 mW" RESC1609X50X30ML08T20 1097.16,678.28 r270 top value=7.15k
R44 "Resistor 51R1 +/-1% 0603 100 mW" RESC1609X50X30ML08T20 790,560 r180 top value=51.1
R45 "Resistor 7K15 +/-1% 0603 100 mW" RESC1609X50X30ML08T20 750,678.28 r270 top value=7.15k
R46 "Resistor 51R1 +/-1% 0603 100 mW" RESC1609X50X30ML08T20 980,560 r180 top value=51.1
R47 "Resistor 51R1 +/-1% 0603 100 mW" RESC1609X50X30ML08T20 1630,660 r180 top value=51.1
R48 "Resistor 7K15 +/-1% 0603 100 mW" RESC1609X50X30ML08T20 931.47,678.28 r270 top value=7.15k
R49 "Resistor 51R1 +/-1% 0603 100 mW" RESC1609X50X30ML08T20 1300,560 r180 top value=51.1
R50 "Resistor 7K15 +/-1% 0603 100 mW" RESC1609X50X30ML08T20 1280,680 r270 top value=7.15k
R51 "Resistor 33K 5% 2512 1W" RESC2512(6432)_M 2590,7050 r90 bottom
R52 "Resistor 10k +/-1% 1206 250 mW" RESC3216X60X45ML15T20 4410,4620 r0 top value=10k
R53 "Resistor 51R1 +/-1% 0603 100 mW" RESC1609X50X30ML08T20 1780,660 r0 top value=51.1
R54 "Resistor 51R1 +/-1% 0603 100 mW" RESC1609X50X30ML08T20 1470,560 r180 top value=51.1
R55 "Resistor 1K24 +/-1% 0603 100 mW" RESC1609X50X30ML08T20 5235,5972.44 r90 bottom value=1.24k
R56 "Resistor 1K24 +/-1% 0603 100 mW" RESC1609X50X30ML08T20 4760,5972.44 r90 bottom value=1.24k
R57 "Resistor 1K24 +/-1% 0603 100 mW" RESC1609X50X30ML08T20 4560,5445 r270 bottom value=1.24k
R58 "Resistor 1K24 +/-1% 0603 100 mW" RESC1609X50X30ML08T20 5437.56,5332.56 r270 bottom value=1.24k
R59 "Resistor 1K24 +/-1% 0603 100 mW" RESC1609X50X30ML08T20 5410,5800 r0 bottom value=1.24k
R60 "Resistor 1K24 +/-1% 0603 100 mW" RESC1609X50X30ML08T20 5035,5445 r270 bottom value=1.24k
R61 "Resistor 330k +/-0.1% 1206 250mW" RESC3216X70X50NL20T25 4490,10190 r90 top
R62 "Resistor 330k +/-0.1% 1206 250mW" RESC3216X70X50NL20T25 4490,10410 r90 top
R63 "Resistor 330k +/-0.1% 1206 250mW" RESC3216X70X50NL20T25 4490,10610 r90 top
R64 "Resistor 330k +/-0.1% 1206 250mW" RESC3216X70X50NL20T25 4630,4130 r90 top
R65 "Resistor 330k +/-0.1% 1206 250mW" RESC3216X70X50NL20T25 4630,4350 r90 top
R66 "Resistor 330k +/-0.1% 1206 250mW" RESC3216X70X50NL20T25 4630,4570 r90 top
R67 "Resistor 18R 5% 2010 750mW" FP-RMCF2010-IPC_A 2960,7370 r180 top
R68 "Resistor 18R 5% 2010 750mW" FP-RMCF2010-IPC_A 2970,1530 r180 top
R69 "Resistor 1K24 +/-1% 0603 100 mW" RESC1609X50X30ML08T20 5437.56,5972.44 r90 top value=1.24k
R70 "Resistor 1K24 +/-1% 0603 100 mW" RESC1609X50X30ML08T20 5437.56,5532.56 r270 top value=1.24k
R71 "Resistor 18R 5% 2010 750mW" FP-RMCF2010-IPC_A 2960,7550 r180 top
R72 "Resistor 18R 5% 2010 750mW" FP-RMCF2010-IPC_A 2660,7550 r180 top
R73 "Resistor 18R 5% 2010 750mW" FP-RMCF2010-IPC_A 2970,1710 r180 top
R74 "Resistor 18R 5% 2010 750mW" FP-RMCF2010-IPC_A 2670,1710 r180 top
R75 "Resistor 18R 5% 2010 750mW" FP-RMCF2010-IPC_A 2660,7370 r180 top
R76 "Resistor 18R 5% 2010 750mW" FP-RMCF2010-IPC_A 2670,1530 r180 top
R77 "Resistor 10k +/-1% 0603 100 mW" RESC1608X55X25ML10T15 310,4950 r0 bottom value=10k
R78 "Resistor 30K1 +/-1% 0603 100 mW" RESC1608X55X25ML10T15 309.53,4860 r180 bottom value=30.1k
R79 "Resistor 47K5 +/-1% 0603 100 mW" RESC1608X55X25ML10T15 310,4420 r0 bottom value=47.5k
R80 "Resistor 47K5 +/-1% 0603 100 mW" RESC1608X55X25ML10T15 509.53,4460 r180 bottom value=47.5k
R81 "Jumper 0603" RESC0603(1608)_L 390,5160 r90 bottom value=0
R82 "Jumper 0603" RESC0603(1608)_L 430,5240 r0 bottom value=0
R83 "Jumper 0603" RESC0603(1608)_L 460,5157.56 r90 bottom value=0
R84 "Resistor 0R +/- 5% 0603 100 mW" RESC1608X55X25ML10T15 6890,6320 r90 top value=0
R85 "Resistor 0R +/- 5% 0603 100 mW" RESC1608X55X25ML10T15 5580,6645 r180 top value=0
R86 "Resistor 47K5 +/-1% 0603 100 mW" RESC1608X55X25ML10T15 735.53,5557 r180 bottom value=47.5k
U1 "AD202KN" FP-AD202KN-MFG 2160,6250 r180 top
U2 "REF3012AIDBZT" DBZ0003A_N 892,5426 r0 bottom
U3 "OPA2141AID" D0008A_L 510,5580 r180 bottom
U4 "CD4051BNSR" NS0016A_M 1420,3020 r0 top
U5 "SN74HC541PW" PW0020A_L 1500,3840 r90 top
U6 "TMCS1101A4BQDR" FP-D0008A-IPC_B 5081,10454 r90 top
U7 "AD202KN" FP-AD202KN-MFG 2455.76,10963.41 r180 top
U8 "AD590KF" FP-F-2-MFG 2840,4225 r270 top
U9 "TMCS1101A4BQDR" FP-D0008A-IPC_B 5025,5135 r90 top
U10 "AD202KN" FP-AD202KN-MFG 2300,5080 r180 top
U11 "AD202KY" FP-Y-10-MFG 2160,6250 r180 top
U12 "AD202KY" FP-Y-10-MFG 2455.76,10953.41 r180 top
U13 "AD202KY" FP-Y-10-MFG 2300,5080 r180 top
U14 "R-785.0-0.5" REPO-R-78XX-3_V 638,11291 r180 top
U15 "OPA2141AID" D0008A_L 375,4663.35 r270 bottom

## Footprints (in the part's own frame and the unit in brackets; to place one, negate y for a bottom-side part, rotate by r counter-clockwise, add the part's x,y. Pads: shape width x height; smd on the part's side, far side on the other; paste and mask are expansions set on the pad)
74437529203221-Footprint-1 [mm]
  rect 8x8.5 smd: 1(0,-8.5) 2(0,8.5)
  silkscreen extent -14,-12.5 14,12.5, body extent -13.65,-11.55 13.65,11.55, height 20
BZG03C200-M3-08-Footprint-1 [mm]
  rect 2.2x2.2 smd: A(-2.25,0) C(2.25,0)
  silkscreen extent -2.25,-1.4 2.25,1.4, body extent -2.6,-1.3 2.6,1.3, height 2.4
"Capacitor 1.2uF 20% 500V X7R-Footprint-1" [mil]
  round 60 hole 27.56: 1(-98.43,0) 2(98.43,0)
  silkscreen extent -197,-83 197,83, body extent -197,-83 197,83, height 453
CAPC1608X90X40NL10T20 [mm] "Chip Capacitor, 2-Leads, Body 1.70x0.90mm, IPC Medium Density"
  rect 0.95x0.95 smd: 1(-0.625,0) 2(0.625,0)
  body extent -0.85,-0.45 0.85,0.45, height 0.9
CAPC2013X95X50ML10T25 [mm] "Chip Capacitor, 2-Leads, Body 2.10x1.35mm, IPC Low Density"
  rect 1.45x1.5 smd: 1(-0.925,0) 2(0.925,0)
  body extent -1.05,-0.67 1.05,0.67, height 0.95
CAPC3225X270X30ML30 [mm] "Chip Capacitor, 2-Leads, Body 3.5x2.7mm, IPC Low Density"
  rect 1.15x2.8 smd: 1(-1.725,0) 2(1.725,0)
  silkscreen extent -0.75,-1.3 0.75,1.3, body extent -1.75,-1.35 1.75,1.35, height 2.7
D0008A_L [mm] "SOIC, 8-Leads, Body 5x4mm, Pitch 1.27mm, IPC High Density"
  rrect18% 1.25x0.55 smd: 1(-2.625,1.905) 2(-2.625,0.635) 3(-2.625,-0.635) 4(-2.625,-1.905) 5(2.625,-1.905) 6(2.625,-0.635) 7(2.625,0.635) 8(2.625,1.905)
  silkscreen extent -2.75,-2.5 1.6,2.85, body extent -3,-2.45 3,2.45, height 1.63
DBZ0003A_N [mm] "SOT23, 3-Leads, Body 3.04x1.4mm, Pitch 0.95mm, IPC Medium Density"
  rrect17% 1x0.6 smd: 1(-1.2,0.95) 2(-1.2,-0.95) 3(1.2,0)
  silkscreen extent -1.32,-1.5 0.7,1.92, body extent -1.26,-1.46 1.26,1.46, height 0.96
DPAK545P1890X510-3N [mm] "D3-PAK, 3-Pads, Body 10.10x11.39mm (max), IPC Medium Density"
  rect 13.6x13.7 smd: D(3.1,0)
  rect 3.6x1.55 smd: G(-8.1,5.45) S(-8.1,-5.45)
  silkscreen extent -8.22,-8.05 -4.1,8.05, body extent -9.62,-7.98 9.28,7.98, height 5.1
FP-5001-MFG [mm]
  round 1.57 hole 1.016: 1(0,0)
  silkscreen extent -1.35,-1.34 1.35,1.34, body extent -1.45,-1.45 1.45,1.45, height 0.25
FP-5002-MFG [mm]
  round 1.57 hole 1.02 paste-1000 mask+0: 1(0,0)
  silkscreen extent -1.35,-1.34 1.35,1.34, body extent -1.45,-1.45 1.45,1.45, height 0.25
FP-AD202KN-MFG [mm]
  rect 1.35x1.35 hole 0.85 paste-1000 mask+0: 1(-22.86,-6.35)
  round 1.35 hole 0.85 paste-1000 mask+0: 2(-20.32,-6.35) 3(-17.78,-6.35) 18(20.32,-6.35) 19(22.86,-6.35) 20(22.86,6.35) 22(17.78,6.35) 36(-17.78,6.35) 37(-20.32,6.35) 38(-22.86,6.35)
  silkscreen extent -27.39,-8.89 26.67,8.89, body extent -26.77,-8.99 26.77,8.99, height 0.25
FP-BLM18-0_15-t0_5-d1_2-IPC_B [mil]
  rect 43.55x37.73 smd paste+0 mask+0: 1(-26.62,0) 2(26.62,0)
  silkscreen extent -48,-35 48,35, body extent -58,-29 58,29, height 10
FP-CRCW2512-e3-MFG [mm]
  rect 1.45x3.5 smd paste+0 mask+0: 1(-3.1,0) 2(3.1,0)
  silkscreen extent -2,-1.65 2,1.65, body extent -3.93,-1.85 3.93,1.85, height 0.25
FP-D0008A-IPC_B [mil]
  rect 85.4x22.92 smd paste+0 mask+0: 1(-93.06,75)
  rrect100% 85.4x22.92 smd paste+0 mask+0: 2(-93.06,25) 3(-93.06,-25) 4(-93.06,-75) 5(93.06,-75) 6(93.06,-25) 7(93.06,25) 8(93.06,75)
  silkscreen extent -162,-97 31,97, body extent -146,-106 146,106, height 10
FP-F-2-MFG [mil]
  rect 19x60 smd paste+0 mask+0: 1(-25,-140) 2(25,-140)
  silkscreen extent -46,-197 46,120, body extent -50,-174 50,124, height 10
FP-IHLP-3232DZ-FP_2_413x5-MFG [mil]
  rect 95x210 smd paste+0 mask+0: 1(-142.5,0) 2(142.5,0)
  silkscreen extent -163,-163 163,163, body extent -194,-166 194,166, height 10
FP-M80-5000000M5-02-333-0-MFG [mm]
  rect 2.5x2.5 hole 1.65 paste-1000 mask+0: A(2,1.8)
  round 2.5 hole 1.65 paste-1000 mask+0: B(-2,1.8)
  round 3.4 hole 2.25 paste-1000 mask+0: MT1(-6.5,2.8) MT2(6.5,2.8)
  silkscreen extent -9.25,-4.4 9.25,5.2, body extent -9.35,-4.5 9.35,4.6, height 0.25
FP-M80-5400642-MFG [mm]
  rect 1.2x1.2 hole 0.7 paste-1000 mask+0: 1(2,5.2)
  round 1.2 hole 0.7 paste-1000 mask+0: 2(0,5.2) 3(-2,5.2) 4(2,3.2) 5(0,3.2) 6(-2,3.2)
  round 2.25 hole 2.25 unplated paste-1000 mask+0: MT1(-5.5,4.2) MT2(5.5,4.2)
  silkscreen extent -8.5,-2.8 8.5,6.48, body extent -8.6,-2.9 8.6,5.9, height 0.25
FP-RDEUE1+0_5-MFG [mm]
  rect 1.2x1.2 hole 0.7 paste-1000 mask+0: 1(-2.5,0)
  round 1.2 hole 0.7 paste-1000 mask+0: 2(2.5,0)
  silkscreen extent -3.85,-2 3.85,2, body extent -3.95,-2.1 3.95,2.1, height 0.25
FP-RMCF2010-IPC_A [mil]
  rect 67.1x110.48 smd paste+0 mask+0: 1(-90.59,0) 2(90.59,0)
  silkscreen extent -45,-55 45,55, body extent -144,-75 144,75, height 10
FP-SMA-MFG [mm]
  rect 2.5x1.7 smd: 1(-2,0) 2(2,0)
  silkscreen extent -3.95,-1.46 2.3,1.46, body extent -2.6,-1.3 2.6,1.3, height 2.4
FP-Y-10-MFG [mm]
  rect 1.25x1.25 hole 0.75 paste-1000 mask+0: 1(-24.054,-1.27)
  round 1.25 hole 0.75 paste-1000 mask+0: 2(-22.784,1.27) 3(-21.514,-1.27) 4(-20.244,1.27) 5(-18.974,-1.27) 6(-17.704,1.27) 31(14.046,-1.27) 32(15.316,1.27) 37(22.098,-1.27) 38(23.368,1.27)
  silkscreen extent -27.14,-3.3 26.42,3.3, body extent -26.52,-3.4 26.52,3.4, height 0.25
IXTA1R6N100D2HV-Footprint-1 [mil]
  rect 430x340 smd: D(0,160)
  rect 60x120 smd: G(-100,-270) S(100,-270)
  silkscreen extent -225,-330 225,340, body extent -182,-323 182,296, height 173
IXTN32P60P-Footprint-1 [mil]
  oct 325x412.5 hole 177.2 copper offset 0,43.75: D(-295,250) S2(295,250)
  oct 325x412.5 hole 177.2 copper offset 0,-43.75: G(-295,-250) S1(295,-250)
  round 0 hole 165 unplated: MNT1(-595,0) MNT2(595,0)
  Top Layer region: 155,-95 155,-95 155,-95 155,-95
  Top Layer region: 150,-60 150,-60 150,-60 150,-60
  silkscreen extent -750,-500 750,500, body extent -749,-490 751,490, height 473
KEMT-D-7343-31-2_L [mm] "Molded TAN Capacitor, 2-Leads, Body 7.6x4.6mm, IPC High Density"
  rect 2.2x2.35 smd: 1(-2.925,0) 2(2.925,0)
  silkscreen extent -4.52,-2.3 3.8,2.3, body extent -3.8,-2.3 3.8,2.3, height 3.1
M80-5400442-Footprint-1 [mm]
  rect 1.2x1.2 hole 0.7 paste-1000 mask+0: 1(1,1)
  round 1.2 hole 0.7 paste-1000 mask+0: 2(-1,1) 3(1,-1) 4(-1,-1)
  round 2.25 hole 2.25 unplated paste-1000 mask+0: MT1(-4.5,0) MT2(4.5,0)
  silkscreen extent -7,-7 7,2.62, body extent -7,-6.9 7,2.2, height 6.11
"MH-M3-Footprint-1 - Oversized MARS2" [mil] "Oversized specific for the MARS2 Project."
  round 390 hole 150: 1(0,0)
NS0016A_M [mm] "SOIC,16-Leads,Body 10.5x5.6mm,Pitch 1.27mm,IPC Low Density"
  rrect15% 1.85x0.65 smd: 1(-3.725,4.445) 2(-3.725,3.175) 3(-3.725,1.905) 4(-3.725,0.635) 5(-3.725,-0.635) 6(-3.725,-1.905) 7(-3.725,-3.175) 8(-3.725,-4.445) 9(3.725,-4.445) 10(3.725,-3.175) 11(3.725,-1.905) 12(3.725,-0.635) 13(3.725,0.635) 14(3.725,1.905) 15(3.725,3.175) 16(3.725,4.445)
  silkscreen extent -3.85,-5.25 2.4,5.44, body extent -2.8,-5.25 2.8,5.25, height 2
PLA143S-Footprint-1 [mil]
  rrect50% 30x70 smd: 1(-100,-175.2) 2(0,-175.2) 3(100,-175.2) 4(100,175.2) 5(0,175.2) 6(-100,175.2)
  silkscreen extent -160,-125 165,125, body extent -173,-198 173,198, height 185
PW0020A_L [mm] "SOP, 20-Leads, Body 6.6x4.5mm, Pitch 0.65mm, IPC High Density"
  rrect25% 1.2x0.4 smd: 1(-2.85,2.925) 2(-2.85,2.275) 3(-2.85,1.625) 4(-2.85,0.975) 5(-2.85,0.325) 6(-2.85,-0.325) 7(-2.85,-0.975) 8(-2.85,-1.625) 9(-2.85,-2.275) 10(-2.85,-2.925) 11(2.85,-2.925) 12(2.85,-2.275) 13(2.85,-1.625) 14(2.85,-0.975) 15(2.85,-0.325) 16(2.85,0.325) 17(2.85,0.975) 18(2.85,1.625) 19(2.85,2.275)
  rrect25% 1.2x0.4 smd mask+0.102: 20(2.85,2.925)
  silkscreen extent -2.97,-3.3 1.85,3.8, body extent -3.21,-3.25 3.21,3.25, height 1
REPO-R-78XX-3_V [mm] "Module, 3-Leads, Body 11.5x7.55mm, Pitch 2.54mm"
  rect 1.75x1.75 hole 1: 1(-2.54,0)
  round 1.75 hole 1: 2(0,0) 3(2.54,0)
  silkscreen extent -5.75,-2.77 5.75,5.55, body extent -5.75,-2 5.75,5.55, height 10.2
RESC0603(1608)_L [mm] "Chip Resistor, Body 1.6x0.8mm, IPC High Density"
  rrect25% 0.66x0.76 smd: 1(-0.7,0) 2(0.7,0)
  silkscreen extent 0,-0.3 0,0.3, body extent -0.8,-0.4 0.8,0.4, height 0.45
RESC1608X55X25ML10T15 [mm] "Chip Resistor, 2-Leads, Body 1.70x0.90mm, IPC Low Density"
  rect 0.8x1 smd: 1(-0.75,0) 2(0.75,0)
  body extent -0.85,-0.45 0.85,0.45, height 0.55
RESC1609X50X30ML08T20 [mm] "Chip Resistor, 2-Leads, Body 1.65x0.95mm, IPC Low Density"
  rect 0.9x1.05 smd: 1(-0.7,0) 2(0.7,0)
  body extent -0.82,-0.48 0.82,0.48, height 0.5
RESC2013X50X35ML15T15 [mm] "Chip Resistor, 2-Leads, Body 2.2x1.4mm, IPC Low Density"
  rect 1.2x1.5 smd: 1(-1.05,0) 2(1.05,0)
  silkscreen extent -0.05,-0.65 0.05,0.65, body extent -1.1,-0.7 1.1,0.7, height 0.5
RESC2512(6432)_M [mm] "Chip Resistor, Body 6.4x3.2mm, IPC Low Density"
  rect 1.45x3.45 smd: 1(-3.1,0) 2(3.1,0)
  silkscreen extent -2,-1.63 2,1.63, body extent -3.25,-1.7 3.25,1.7, height 0.75
RESC3216X60X45ML15T20 [mm] "Chip Resistor, 2-Leads, Body 3.3x1.75mm, IPC Low Density"
  rect 1.35x1.85 smd: 1(-1.525,0) 2(1.525,0)
  silkscreen extent -0.45,-0.82 0.45,0.82, body extent -1.65,-0.87 1.65,0.87, height 0.6
RESC3216X70X50NL20T25 [mm] "Chip Resistor, 2-Leads, Body 3.20x1.60mm, IPC Medium Density"
  rect 1.3x1.8 smd: 1(-1.4,0) 2(1.4,0)
  silkscreen extent -0.35,-0.8 0.35,0.8, body extent -1.7,-0.9 1.7,0.9, height 0.7
RESC5025X06M [mm] "Chip Resistor, 2-Leads, Body 5.00x2.50mm, IPC Low Density"
  rect 1.4x2.75 smd: 1(-2.4,0) 2(2.4,0)
  silkscreen extent -1.3,-1.27 1.3,1.28, body extent -2.55,-1.32 2.55,1.33, height 0.65
RS3-2415S_H3-Footprint-1 [mm]
  round 1.75 hole 1.1: 1(-8.89,2.54) 2(-6.35,2.54) 3(-3.81,2.54) 5(1.27,2.54) 6(3.81,2.54) 7(6.35,2.54) 8(8.89,2.54)
  silkscreen extent -10.89,-3.46 10.91,5.74, body extent -10.9,-3.33 10.9,5.87, height 11.1
SMTC-ESQ-132-14-X-D [mm] "Elevated Socket, 2x32 Pins, Vertical, 2.54mm Pitch, Female"
  rect 1.55x1.55 hole 1.02: 1(0,0)
  round 1.55 hole 1.02: 2(0,-2.54) 3(2.54,0) 4(2.54,-2.54) 5(5.08,0) 6(5.08,-2.54) 7(7.62,0) 8(7.62,-2.54) 9(10.16,0) 10(10.16,-2.54) 11(12.7,0) 12(12.7,-2.54) 13(15.24,0) 14(15.24,-2.54) 15(17.78,0) 16(17.78,-2.54) 17(20.32,0) 18(20.32,-2.54) 19(22.86,0) 20(22.86,-2.54) 21(25.4,0) 22(25.4,-2.54) 23(27.94,0) 24(27.94,-2.54) 25(30.48,0) 26(30.48,-2.54) 27(33.02,0) 28(33.02,-2.54) 29(35.56,0) 30(35.56,-2.54) 31(38.1,0) 32(38.1,-2.54) 33(40.64,0) 34(40.64,-2.54) 35(43.18,0) 36(43.18,-2.54) 37(45.72,0) 38(45.72,-2.54) 39(48.26,0) 40(48.26,-2.54) 41(50.8,0) 42(50.8,-2.54) 43(53.34,0) 44(53.34,-2.54) 45(55.88,0) 46(55.88,-2.54) 47(58.42,0) 48(58.42,-2.54) 49(60.96,0) 50(60.96,-2.54) 51(63.5,0) 52(63.5,-2.54) 53(66.04,0) 54(66.04,-2.54) 55(68.58,0) 56(68.58,-2.54) 57(71.12,0) 58(71.12,-2.54) 59(73.66,0) 60(73.66,-2.54) 61(76.2,0) 62(76.2,-2.54) 63(78.74,0) 64(78.74,-2.54)
  silkscreen extent -1.53,-3.74 80.27,1.2, body extent -1.52,-3.81 80.26,1.27, height 11.05

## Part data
C1 C2 C4 C31 C33 C38 C39 C40 C41: library part CMP-001-00088-9, "10uF Solid MnO2 Tantalum Electrolytic Capacitor; 50 V dc +/-10%; T491 Series", Capacitance=10uF, Case Code (Imperial)=2917, Dielectric Material=Tantalum, ESR (Equivalent Series Resistance)=800mR, Leakage Current=5uA, Manufacturer=KEMET, Max Operating Temperature=125°C, Min Operating Temperature=-55°C, Package Quantity=20, Ripple Current=433mA, Tolerance=10%, Voltage=50V
C3: library part CMP-001-00111-10, "Chip Capacitor, 330pF, 10%, 50 V, X7R 0805 (2012 Metric)", Capacitance=330pF, Capacitor Type=Ceramic, Case/Package=0805, Dielectric=X7R, Max Operating Temperature=125°C, Min Operating Temperature=-55°C, Tolerance=10%, Voltage Rating=50V
C5 C6 C7 C8 C9 C10: library part CMP-001-00084-11, "Cap Ceramic 0.22uF 1000V X7R 20% Radial 5mm 125°C Bulk", Capacitance=220nF, Case/Package=Radial, Dielectric=X7R, Manufacturer PN=RDER73A224MUB1H03B, Max Operating Temperature=125°C, Min Operating Temperature=-55°C, Resistor Type=Ceramic, Tolerance=20%, Voltage=1kV
C11: library part CMP-001-00182-8, "Chip Capacitor, 2.2uF, 10%, 50 V, X7R 1210 (3225 Metric)", Capacitance=2.2uF, Capacitor Type=Ceramic, Case/Package=1210, Dielectric=X7R, Max Operating Temperature=125°C, Min Operating Temperature=-55°C, Tolerance=10%, Voltage Rating=50V
C12 C13 C14 C15 C16 C17 C18 C19 C20 C21 C22 C23 C24 C25 C26 C27 C28 C29 C30 C42 C43 C44 C45 C46: library part CMP-001-00017-14, "Chip Capacitor, 100 nF, +/- 10%, 50 V, 0603 (1608 Metric)", Capacitance=100nF, Capacitor Type=Ceramic, Case/Package=0603, Max Operating Temperature=125°C, Min Operating Temperature=-55°C, Tolerance=10%, Voltage Rating=50V
C32: library part CMP-001-00183-9, "Chip Capacitor, 4.7uF, 10%, 50 V, X7R 1210 (3225 Metric)", Capacitance=4.7uF, Capacitor Type=Ceramic, Case/Package=1210, Dielectric=X7R, Max Operating Temperature=125°C, Min Operating Temperature=-55°C, Tolerance=10%, Voltage Rating=50V
C34 C35 C36 C37: library part CMP-001-00207-8, "Dipped Radial Lead Multilayer Ceramic Capacitors", Capacitance=1.2uF, Case/Package=Radial, Manufacturing PN=KTD501B125M76A0T00, Max Operating Temperature=125°C, Min Operating Temperature=-55°C, Tolerance=20%, Voltage Rating=500V
D1 D2 D7 D8 D9 D10: library part CMP-004-00031-4, "Vz=15V 14.25V~15.75V Izt=50mA P=1W", Case/Package=SMA, Forward Voltage=1.2V, Max Operating Temperature=150°C, Max Power Dissipation=1W, Max Reverse Current=1uA, Min Operating Temperature=-65°C, Test Current=50mA, Tolerance=5%, Voltage Rating (DC)=15
D3 D4 D5 D6: library part CMP-004-00032-3, "Zener Diode Single 200V 6% 500Ohm 3000mW 2-Pin SMA T/R", Current - Reverse Leakage @ Vr="1 µA @ 150 V", Operating Temperature="150°C (TJ)", Package / Case=DO-214AC,SMA, Power - Max=1.25W, Tolerance=±6%, Voltage - Forward (Vf) (Max) @ If="1.2 V @ 500 mA", Voltage - Zener (Nom) (Vz)=200V
DC1: library part CMP-019-00053-2, "3W DC/DC-Converter 'ECONOLINE' SIP8 3kV reg 2: 1; V. In: 18-36; V. Out: 15; mA. Out: 200", Case/Package=SIP, Current=200mA, Isolation Voltage=3kV, Max Input Voltage=36V, Max Operating Temperature=71°C, Max Output Voltage=15V, Max Power Dissipation=3W, Min Input Voltage=18V, Min Operating Temperature=-40°C, Nominal Input Voltage=24V, Voltage Input=18V-36V
FB1 FB2: library part CMP-00000-1, "Ferrite Beads Multi-Layer 120Ohm 25% 100MHz 3A 0.025Ohm DCR 0603 T/R", Case Code (Imperial)=0603, Case Code (Metric)=1608, Current Rating=3A, DC Resistance (DCR)=25mR, Frequency=100MHz, Max Operating Temperature=125°C, Min Operating Temperature=-55°C, Package Quantity=1, Tolerance=25%
J1 J2 J4 J5 J6 J7: library part CMP-002-00075-3, "Conn Header R/a 2POS 4MM", Color=Black, Contact Resistance=25mR, Current Rating=40A, Insulation Resistance=100MR, Manufacturer=Harwin, Max Operating Temperature=125°C, Maximum Voltage=800V, Min Operating Temperature=-55°C
J3: library part CMP-002-00095-3, "HARWIN - M80-5400442 - Wire-To-Board Connector, 2 mm, 4 Contacts, Header, Datamate J-Tek M80 Series, Through Hole, 2 Rows", Color=Black, Contact Resistance=25mR, Current Rating=2.2A, Insulation Resistance=100MR, Manufacturer=Harwin, Max Operating Temperature=125°C, Maximum Voltage=800V, Min Operating Temperature=-55°C
J8 J9: library part CMP-002-00093-2, "Conn Elevated Socket SKT 64 POS 2.54mm Solder ST Top Entry Thru-Hole Tube", Color=Black, Contact Resistance=10mR, Current Rating=6.9A, Max Operating Temperature=125°C, Max Voltage Rating (AC)=550V, Min Operating Temperature=-55°C, Package Quantity=1
J10: library part CMP-002-00076-5, "Conn Header R/a 6POS 2MM", Color=Black, Contact Resistance=25mR, Current Rating=3A, Insulation Resistance=100MR, Manufacturer=Harwin, Max Operating Temperature=125°C, Max Voltage Rating (AC)=120V, Maximum Voltage=800V, Min Operating Temperature=-55°C
J11 J12 J13 J14 J15 J16 J17 J18 J19 J20 J21 J22 J23 J24 J25 J26 J27 J28 J29 J30 J31 J32 J33 J34 J35 J39 J40: library part CMP-002-00083-3, "TEST POINT PC MINI .040D WHITE", Color=White
J36 J37 J38: library part CMP-001-0002-3, "TEST POINT PC MINI .040D BLACK", Color=Black
K1 K2 K3 K4 K5 K6 K7 K8: library part CMP-008-00005-3, "Relay SSR 50mA 1.4V DC-IN 0.1A 600V AC/DC-OUT 6-Pin PDIP SMD Tube", Case/Package=SMD/SMT, Input Current=50mA, Isolation Voltage=4kV, Load Current=100mA, Max Operating Temperature=85°C, Max Output Voltage=600V, Max Power Dissipation=800mW, Min Operating Temperature=-40°C, On-State Resistance=50R
L1 L4: library part CMP-006-00023-3, "Inductor Power Shielded Wirewound 5.6uH 20% 100KHz Powdered Iron 6.8A 0.0355Ohm DCR 3232 T/R", Case/Package=3232, Current=6.8A, DC Resistance (DCR)=35.5mR, Inductance=5.6uH, Inductance Tolerance=20%, Max DC Current=16.7A, Max Operating Temperature=125°C, Min Operating Temperature=-55°C, Self Resonant Frequency=18MHz, Test Frequency=100kHz
L2 L3: library part CMP-006-00021-5, "Fixed Ind 220UH 8.8A 36.45 Mohm", Case/Package=Nonstandard, Current=8.8A, DC Resistance (DCR)=36.45mR, Inductance=220uH, Max Operating Temperature=125°C, Min Operating Temperature=-40°C, Resistance=36.45Mohm, Resistor Type=Wirewound, Saturation Current=5.3A, Self Resonant Frequency=2.8MHz, Test Frequency=100kHz, Tolerance=20%
MH1 MH2 MH3 MH4 MH5 MH6 MH7 MH8 MH9 MH10 MH11: library part CMP-00028-00015-1, "MARS2 Project 6-32 Mounting Hole Plated ."
Q1 Q4 Q5 Q8: library part CMP-013-00041-4, "Mosfet P-ch 600V 32A SOT227B", Case/Package=SOT-227-4, Continuous Drain Current (ID)=32A, Drain to Source Breakdown Voltage=600V, Drain to Source Resistance=350mR, Input Capacitance=11.1nF, Max Operating Temperature=150°C, Max Power Dissipation=890W, Min Operating Temperature=-55°C, Voltage=600
Q2 Q3: library part CMP-013-00034-5, "Single P-Channel 600 V 720 mOhm 460 W Power Mosfet - TO-268", Case/Package=TO-268-3, Continuous Drain Current (ID)=16A, Current=-16A, Drain to Source Resistance=720MR, Drain to Source Voltage (Vdss)=600V, Input Capacitance=5.12nF, Max Power Dissipation=460W
Q6 Q7: library part CMP-013-00046-3, "Mosfet N-ch 1000V 1.6A TO263HV", Case/Package=TO-263-3, Continuous Drain Current (ID)=1.6A, Drain to Source Voltage (Vdss)=1kV, Input Capacitance=645pF, Max Operating Temperature=150°C, Max Power Dissipation=100W, Min Operating Temperature=-55°C
R1 R2: library part CMP-009-01195-2, "Res Thick Film 2512 1 Ohm 1% 1W ±100ppm/°C Molded SMD SMD", Case Code (Imperial)=2512, Manufacture PN=CRCW25121R00FKEG, Max Operating Temperature=155°C, Max Power Dissipation=1W, Min Operating Temperature=-55°C, Ratings=AEC-Q200, Resistance=1R, Resistance Tolerance=1%, Resistor Type="Thick Film", Temperature Coefficient=100ppm/°C, Voltage Rating=500V
R3 R4 R5 R6: library part CMP-009-00025-6, "Chip Resistor, 100 KOhm, +/- 1%, 0.25 W, -55 to 155 degC, 1206 (3216 Metric)", Case/Package=1206, Max Operating Temperature=155°C, Min Operating Temperature=-55°C, Power=250mW, Tolerance=1%, Voltage Rating=200V
R7 R8 R30 R31 R32 R33 R34 R35 R36 R37 R39 R51: library part CMP-009-01196-1, "Res Thick Film 2512 33K Ohm 5% 1W ±200ppm/°C Molded SMD SMD Blister T/R", Case Code (Imperial)=2512, Manufacturer PN=CRCW251233K0JNEG, Max Operating Temperature=155°C, Max Power Dissipation=1W, Min Operating Temperature=-55°C, Resistance=33kR, Resistance Tolerance=5%, Resistor Type="Thick Film", Temperature Coefficient=200ppm/°C, Voltage Rating=500V
R9 R17 R18 R19 R20 R79 R80 R86: library part CMP-009-00999-3, "Chip Resistor, 47.5k Ohm, +/- 1%, 0.1 W, -55 to 155 degC, 0603 (1608 Metric)", Case/Package=0603, Max Operating Temperature=155°C, Min Operating Temperature=-55°C, Power=100mW, Tolerance=1%, Voltage Rating=75V
R10 R38: library part CMP-009-01250-3, "Res Thick Film 2010 1M Ohm 1% 3/4W ±100ppm/°C Molded SMD SMD Embossed T/R", Case/Package=2010, Max Operating Temperature=155°C, Max Power Dissipation=750mW, Min Operating Temperature=-55°C, Resistance Tolerance=1%, Resistor Type="Thick Film", Temperature Coefficient=100ppm/°C, Voltage Rating=200V
R13 R14: library part CMP-009-00001-7, "Chip Resistor, 0 Ohm, +/- 1%, 125 mW, -55 to 155 degC, 0805 (2012 Metric)", Case/Package=0805, Max Operating Temperature=155°C, Min Operating Temperature=-55°C, Power=125mW, Tolerance=1%, Voltage Rating=150V
R15 R16: library part CMP-009-00594-2, "Chip Resistor, 2.43 KOhm, +/- 1%, 0.1 W, -55 to 155 degC, 0603 (1608 Metric)", Case/Package=0603, Max Operating Temperature=155°C, Min Operating Temperature=-55°C, Power=100mW, Tolerance=1%, Voltage Rating=75V
R21 R22 R23 R24 R25 R26 R27 R28 R29: library part CMP-009-00023-6, "Chip Resistor, 100 KOhm, +/- 1%, 0.1 W, -55 to 155 degC, 0603 (1608 Metric)", Case/Package=0603, Max Operating Temperature=155°C, Min Operating Temperature=-55°C, Power=100mW, Tolerance=1%, Voltage Rating=50V
R40 R52: library part CMP-009-00016-6, "Chip Resistor, 10 KOhm, +/- 1%, 0.25 W, -55 to 155 degC, 1206 (3216 Metric)", Case/Package=1206, Max Operating Temperature=155°C, Min Operating Temperature=-55°C, Power=250mW, Tolerance=1%, Voltage Rating=200V
R41 R42 R44 R46 R47 R49 R53 R54: library part CMP-009-01135-1, "Chip Resistor, 51.1 Ohm, +/- 1%, 0.1 W, -55 to 155 degC, 0603 (1608 Metric)", Case/Package=0603, Max Operating Temperature=155°C, Min Operating Temperature=-55°C, Power=100mW, Tolerance=1%, Voltage Rating=75V
R43 R45 R48 R50: library part CMP-009-00865-4, "Chip Resistor, 7.15k Ohm, +/- 1%, 0.1 W, -55 to 155 degC, 0603 (1608 Metric)", Case/Package=0603, Max Operating Temperature=155°C, Min Operating Temperature=-55°C, Power=100mW, Tolerance=1%, Voltage Rating=75V
R55 R56 R57 R58 R59 R60 R69 R70: library part CMP-009-00795-4, "Chip Resistor, 1.24k Ohm, +/- 1%, 0.1 W, -55 to 155 degC, 0603 (1608 Metric)", Case/Package=0603, Max Operating Temperature=155°C, Min Operating Temperature=-55°C, Power=100mW, Tolerance=1%, Voltage Rating=75V
R61 R62 R63 R64 R65 R66: library part CMP-009-01192-1, "Res Thin Film 1206 330K Ohm 0.1% 1/4W ±25ppm/°C Molded SMD SMD Punched Carrier T/R", Case/Package=1206, Manufacture PN=ERA8AEB334V, Max Operating Temperature=155°C, Max Power Dissipation=250mW, Resistance=330kR, Resistance Tolerance=0.1%, Temperature Coefficient=25ppm/°C, Voltage Rating=300V
R67 R68 R71 R72 R73 R74 R75 R76: library part CMP-009-01190-1, "Res Thick Film 2010 18 Ohm 5% 3/4W ±100ppm/°C Molded SMD SMD Plastic T/R", Case Code (Imperial)=2010, Manufacturer PN=RMCF2010JT18R0, Max Operating Temperature=155°C, Max Power Dissipation=750mW, Min Operating Temperature=-55°C, Ratings=AEC-Q200, Resistance=18R, Resistor Type="Thick Film", Temperature Coefficient=200ppm/°C, Tolerance=5%
R77: library part CMP-009-00017-7, "Chip Resistor, 10 KOhm, +/- 1%, 01 W, -55 to 155 degC, 0603 (1608 Metric)", Case/Package=0603, Max Operating Temperature=155°C, Min Operating Temperature=-55°C, Power=100mW, Tolerance=1%, Voltage Rating=50V
R78: library part CMP-009-00980-3, "Chip Resistor, 30.1k Ohm, +/- 1%, 0.1 W, -55 to 155 degC, 0603 (1608 Metric)", Case/Package=0603, Max Operating Temperature=155°C, Min Operating Temperature=-55°C, Power=100mW, Tolerance=1%, Voltage Rating=75V
R81 R82 R83: library part CMP-009-00175-3, Case/Package=0603, Max Operating Temperature=155°C, Min Operating Temperature=-55°C
R84 R85: library part CMP-009-00006-6, "Chip Resistor, 0 Ohm, 0.1 W, -55 to 155 degC, 0603 (1608 Metric)", Case/Package=0603, Max Operating Temperature=155°C, Min Operating Temperature=-55°C, Power=100mW, Tolerance=5%, Voltage Rating=50V
U1 U7 U10: library part CMP-014-00004-2, "SP Amp Isolated Amp Single 16.5 Volt 11-Pin PDIP", Case/Package=PDIP, Input Bias Current=30pA, Input Offset Voltage (Vos)=5mV, Input Resistance=2GR, Isolation Voltage=1.5kV, Max Operating Temperature=85°C, Max Supply Current=5mA, Max Supply Voltage=16.5V, Min Operating Temperature=-40°C, Min Supply Voltage=13.5V, Nominal Supply Current=35mA, Operating Supply Voltage=15V, Output Current per Channel=400uA, Voltage Gain=40dB
U2: library part CMP-019-00057-2, "1.25V 50ppm/Degrees C, 50uA in SOT23-3 Series (Bandgap) Voltage Reference 3-SOT-23 -40 to 125", Case/Package=SOT-23, Max Input Voltage=5.5V, Max Operating Temperature=125°C, Max Output Current=25mA, Max Output Voltage=1.25V, Max Supply Current=50uA, Min Input Voltage=1.8V, Min Operating Temperature=-40°C, Min Output Voltage=1.248V, Nominal Supply Current=42uA, Temperature Coefficient=50ppm/°C, Tolerance=0.2%
U3 U15: library part CMP-014-00005-2, "Dual, 10MHz, Single Supply, Low Noise, JFET Precision Amplifier 8-SOIC -40 to 125", Case/Package=D, Input Bias Current=20pA, Input Offset Voltage (Vos)=1mV, Max Dual Supply Voltage=18V, Max Frequency=1MHz, Max I/O Voltage=3.5mV, Max Operating Temperature=125°C, Max Supply Voltage=36V, Min Dual Supply Voltage=2.25V, Min Operating Temperature=-40°C, Min Supply Voltage=4.5V, Nominal Supply Current=2.3mA, Operating Supply Current=1.8mA, Output Current=36mA, Power Supply Rejection Ratio (PSRR)=137.07dB, Voltage Gain=126dB
U4: library part CMP-016-00011-2, "1 Circuit IC Switch 8:1 240 Ohm 16-SO", Case/Package=SOIC, Max Dual Supply Voltage=9V, Max Operating Temperature=125°C, Max Supply Voltage=20V, Min Dual Supply Voltage=2.5V, Min Operating Temperature=-55°C, Min Supply Voltage=3V, Nominal Supply Current=100uA, On-State Resistance=240R, Operating Supply Current=80nA, Operating Supply Voltage=18V
U5: library part CMP-016-00012-2, "Buffer/Line Driver 8-CH Non-Inverting 3-ST CMOS 20-Pin TSSOP Tube", Case/Package=TSSOP, High Level Output Current=-7.8mA, Low Level Output Current=7.8mA, Max Operating Temperature=85°C, Max Supply Voltage=6V, Min Operating Temperature=-40°C, Min Supply Voltage=2V, Operating Supply Voltage=5V, Package Quantity=70, Quiescent Current=8uA
U6 U9: library part CMP-010-00025-5, "Precision isolated bidirectional current sensor with Vsupply ratiometric reference 8-SOIC -40 to 125", Case/Package=SOIC, Current Sensing=5.6A, Frequency=80kHz, Max Operating Temperature=125°C, Max Supply Current=6mA, Min Operating Temperature=-40°C
U8: library part CMP-010-00024-2, "SENSOR ANALOG -55C-150C 2FLATPK / Two-Twrminal IC Temperature Transducer", Case/Package=Ceramic, Forward Voltage=44V, Max Operating Temperature=150°C, Max Supply Voltage=30V, Min Operating Temperature=-55°C, Min Supply Voltage=4V, Output Current=298.2uA
U11 U12 U13: library part CMP-014-00002-1, "Amplifier; Isolation Amplifier; 15 V + 10%; 2 kHz; + 5 V; 130 dB; SIP; -40 degC"
U14: library part CMP-019-00062-2, "0.5A DC/DC-Converter 'INNOLINE' SIP3 reg; V. In: 6.5-32; V. Out: 5.0; mA. Out: 500", Case/Package=SIP, Current - Output 1=500mA, Isolation Voltage=2kV, Max Input Voltage=32V, Max Operating Temperature=85°C, Max Output Power=2.5W, Max Output Voltage=5V, Max Power Dissipation=3W, Min Input Voltage=6.5V, Min Operating Temperature=-40°C, Nominal Input Voltage=24V, Switching Frequency=380kHz

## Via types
v1: diameter 25, hole 15, Top Layer to Bottom Layer, 92 vias
v2: diameter 50, hole 28, Top Layer to Bottom Layer, 34 vias
v3: diameter 25, hole 10, Top Layer to Bottom Layer, 1 vias

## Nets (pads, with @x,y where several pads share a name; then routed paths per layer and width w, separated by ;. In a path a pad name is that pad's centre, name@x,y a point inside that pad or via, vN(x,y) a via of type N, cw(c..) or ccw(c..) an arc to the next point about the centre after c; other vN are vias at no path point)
24V_UNSWCH_BUS_CURRENT: J9.18
BAYCAT_3V3: J8.18
CHASIS1: FB1.1
  other v1: 6670,580 6830,580 6670,660 6750,660 6830,660 6670,750 6750,750 6830,750
CHASIS2: FB2.1
  other v1: 6659,11233 6739,11233 6819,11233 6659,11313 6739,11313 6819,11313 6659,11383 6819,11383
DIO_SPARE_0: J8.2
DIO_SPARE_1: J8.4
DIO_SPARE_2: J8.6
DIO_SPARE_3: J8.8
DIO_SPARE_4: J8.10
DIO_SPARE_5: J8.12
DIO_SPARE_6: J8.14
DIO_SPARE_7: J8.16
FAULT_MUX_A: J9.58
FAULT_MUX_B: J9.60
FAULT_MUX_C: J9.62
FAULT_SENSE_HCB: J9.55
FAULT_SENSE_IPB1: J9.51
FAULT_SENSE_IPB2: J9.53
GF_SOURCE_SEL_ENn: J9.7 J27.1 R21.2 U4.6 U5.1 U5.19 | length 6065.2
  Top Layer w10: J27.1@1370,2670 v1(1370,2950) 1365,2945 U4.6@1273.35,2945 1220.91,2945 1150.59,2874.69 1150.59,2841.06 R21.2@1149.53,2840 1149.53,2725.93 2060,1815.46 2060,640 2140,560 3540,560 3643.51,456.49 3643.51,356.49 J9.7@3700,300 ; v1(1370,3670) 1370,3697.2 1384.84,3712.05 U5.1@1384.84,3727.8 ; v1(1410,3880) 1410,3951.77 U5.19@1410.43,3952.2
  Bottom Layer w10: v1(1370,2950) v1(1370,3670) 1370,3840 v1(1410,3880)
